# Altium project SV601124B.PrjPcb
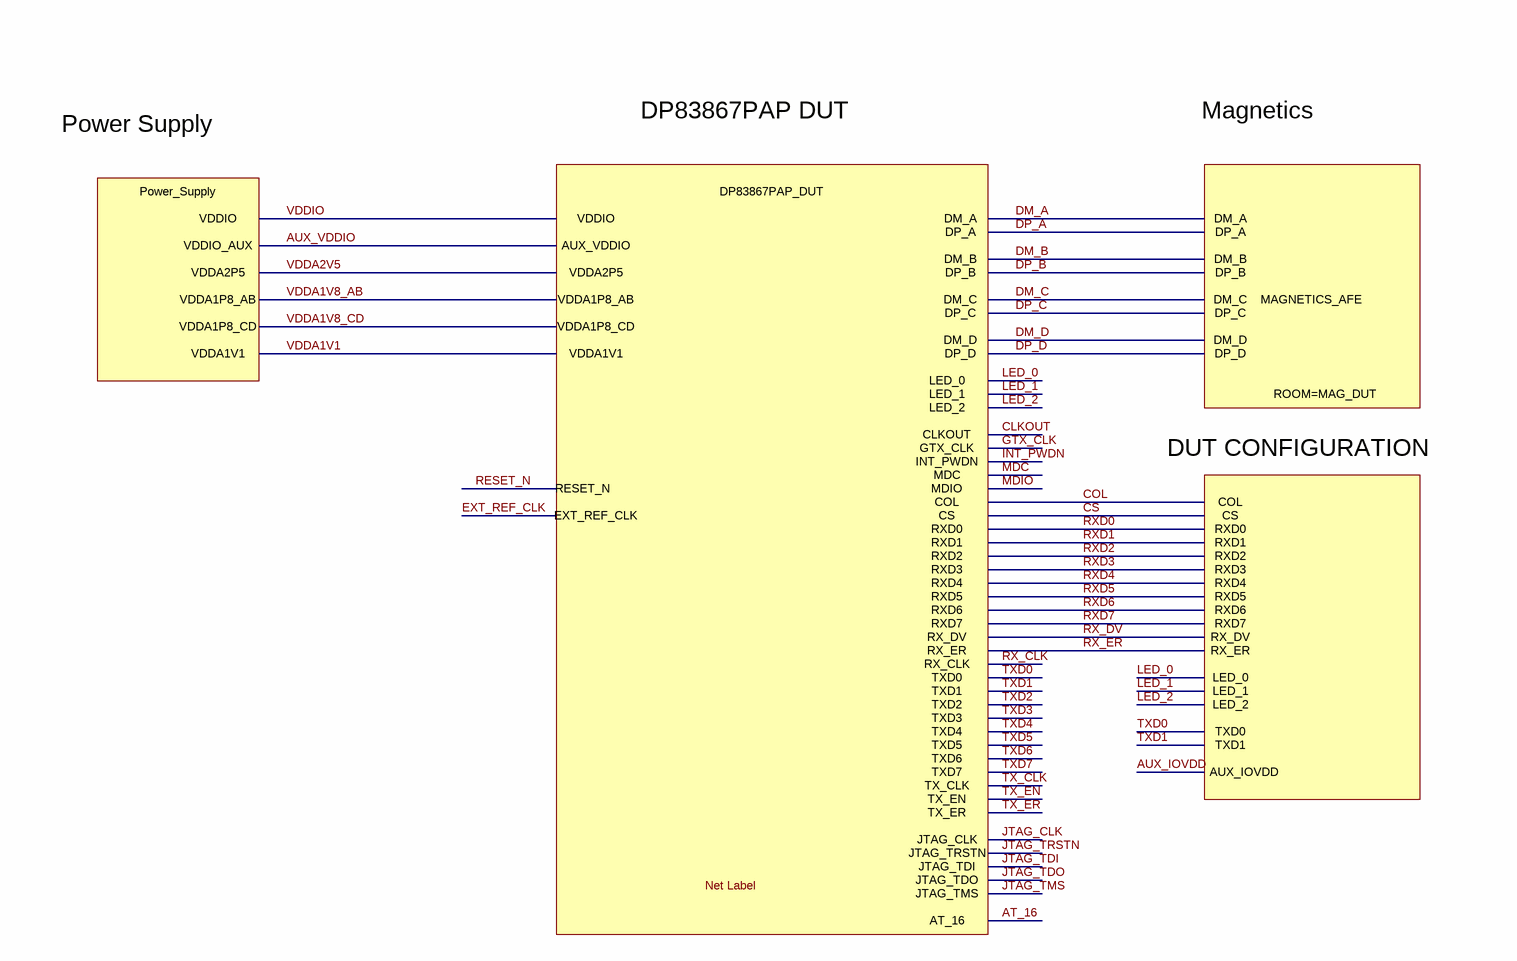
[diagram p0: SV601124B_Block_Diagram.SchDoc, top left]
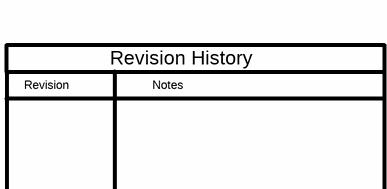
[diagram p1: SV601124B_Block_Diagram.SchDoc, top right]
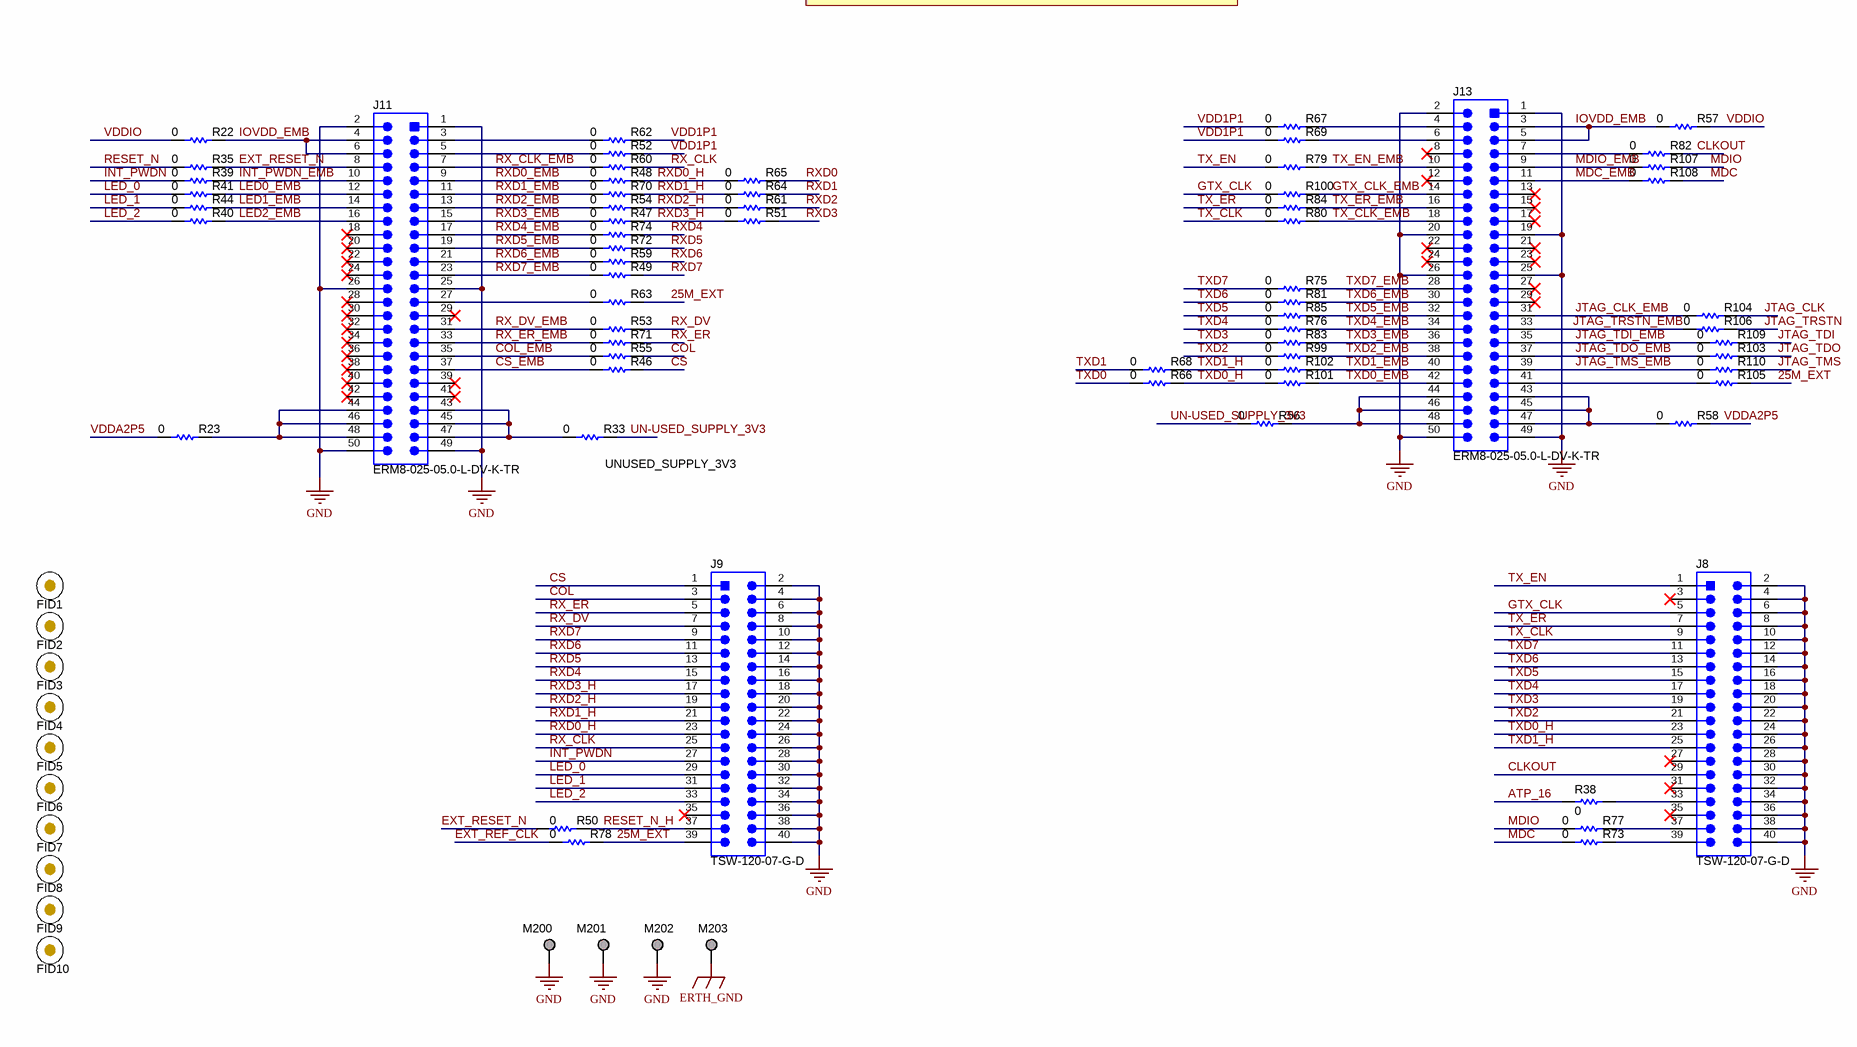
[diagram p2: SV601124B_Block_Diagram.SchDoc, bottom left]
TID: N/A; TechSupport: http://www.ti.com/support; SCH_Rev: B; PRJ_Title: DP83867IRPAP-EVM; PRJ_Number: SV601124; PRJ_Engineer: Dan Suckow; PRJ_Customer: Public Release; PCB_Rev: B; PCB_Layout: Matthew Dillingham; CopyrightYear: 2014
5 sheets, 246 parts. Net scope: global (net labels, ports and power ports of the same name join across sheets).
Board file: SV601124B.PcbDoc
Sheets:
  SV601124B_Block_Diagram.SchDoc
  SV601124B_DP83867IRPAP.SchDoc
  SV601124B_Power_Supply.SchDoc
  SV601124B_Configuration pins.SchDoc
  SV601124B_Magnetics.SchDoc

## Sheet SV601124B_Block_Diagram.SchDoc
size 431 x 406 mm; Date: Not shown in title block; ApprovedBy: Not shown in title block; CheckedBy: Not shown in title block; Author: Not shown in title block; CompanyName: Not shown in title block; Engineer: Not shown in title block; Organization: Not shown in title block; Address1: Not shown in title block; Address2: Not shown in title block; Address3: Not shown in title block; Address4: Not shown in title block; DocumentNumber: 1; Revision: Use project parameter SCH_Rev; SheetNumber: 1; SheetTotal: 3; PageSetup: Record=PageOptions¦CenterHorizontal=True¦CenterVertical=True¦PrintScale=1.00¦XCorrection=1.00¦YCorrection=1.00¦PrintKind=0¦BorderSize=5000000¦LeftOffset=0¦BottomOffset=0¦Orientation=2¦PaperLength=1000¦PaperWidth=1000¦Scale=100¦PaperSource=15¦PrintQuality=600¦MediaType=1¦DitherType=10¦PrintScaleMode=1¦PaperKind=Letter

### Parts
FID1  Fiducial  [Fiducial10-20]  (value not drawn)
FID2  Fiducial  [Fiducial10-20]  (value not drawn)
FID3  Fiducial  [Fiducial10-20]  (value not drawn)
FID4  Fiducial  [Fiducial10-20]  (value not drawn)
FID5  Fiducial  [Fiducial10-20]  (value not drawn)
FID6  Fiducial  [Fiducial10-20]  (value not drawn)
FID7  Fiducial  [Fiducial10-20]  (value not drawn)
FID8  Fiducial  [Fiducial10-20]  (value not drawn)
FID9  Fiducial  [Fiducial10-20]  (value not drawn)
FID10  Fiducial  [Fiducial10-20]  (value not drawn)
J8  TSW-120-07-G-D  [TSW-120-07-G-D]
J9  TSW-120-07-G-D  [TSW-120-07-G-D]
J11  ERM8-025-05.0-L-DV-K-TR  [SAMTEC_ERM8-025-05_0-L-DV-K-TR]
J13  ERM8-025-05.0-L-DV-K-TR  [SAMTEC_ERM8-025-05_0-L-DV-K-TR]
M200  TESTPOINT  [TESTPOINT]  (value not drawn)  (no BOM)
M201  TESTPOINT  [TESTPOINT]  (value not drawn)  (no BOM)
M202  TESTPOINT  [TESTPOINT]  (value not drawn)  (no BOM)
M203  TESTPOINT  [TESTPOINT]  (value not drawn)  (no BOM)
R22  ValueDisplayed: 0  [0603]  (hidden comment: RC0603JR-070RL)
R23  ValueDisplayed: 0  [0603L]  (hidden comment: RC0603JR-070RL)
R33  ValueDisplayed: 0  [0603L]  (hidden comment: RC0603JR-070RL)
R35  ValueDisplayed: 0  [0402L]  (hidden comment: CRCW04020000Z0ED)
R38  ValueDisplayed: 0  [0402]  (hidden comment: CRCW04020000Z0ED)
R39  ValueDisplayed: 0  [0402L]  (hidden comment: CRCW04020000Z0ED)
R40  ValueDisplayed: 0  [0402]  (hidden comment: CRCW04020000Z0ED)
R41  ValueDisplayed: 0  [0402L]  (hidden comment: CRCW04020000Z0ED)
R44  ValueDisplayed: 0  [0402]  (hidden comment: CRCW04020000Z0ED)
R46  ValueDisplayed: 0  [0402]  (hidden comment: CRCW04020000Z0ED)
R47  ValueDisplayed: 0  [0402L]  (hidden comment: CRCW04020000Z0ED)
R48  ValueDisplayed: 0  [0402L]  (hidden comment: CRCW04020000Z0ED)
R49  ValueDisplayed: 0  [0402]  (hidden comment: CRCW04020000Z0ED)
R50  ValueDisplayed: 0  [0402]  (hidden comment: CRCW04020000Z0ED)
R51  ValueDisplayed: 0  [0201L]  (hidden comment: ERJ-1GE0R00C)
R52  ValueDisplayed: 0  [0603]  (hidden comment: RC0603JR-070RL)
R53  ValueDisplayed: 0  [0402]  (hidden comment: CRCW04020000Z0ED)
R54  ValueDisplayed: 0  [0402L]  (hidden comment: CRCW04020000Z0ED)
R55  ValueDisplayed: 0  [0402]  (hidden comment: CRCW04020000Z0ED)
R56  ValueDisplayed: 0  [0603]  (hidden comment: RC0603JR-070RL)
R57  ValueDisplayed: 0  [0603L]  (hidden comment: RC0603JR-070RL)
R58  ValueDisplayed: 0  [0603]  (hidden comment: RC0603JR-070RL)
R59  ValueDisplayed: 0  [0402]  (hidden comment: CRCW04020000Z0ED)
R60  ValueDisplayed: 0  [0402]  (hidden comment: CRCW04020000Z0ED)
R61  ValueDisplayed: 0  [0201L]  (hidden comment: ERJ-1GE0R00C)
R62  ValueDisplayed: 0  [0603]  (hidden comment: RC0603JR-070RL)
R63  ValueDisplayed: 0  [0603L]  (hidden comment: RC0603JR-070RL)
R64  ValueDisplayed: 0  [0201L]  (hidden comment: ERJ-1GE0R00C)
R65  ValueDisplayed: 0  [0201L]  (hidden comment: ERJ-1GE0R00C)
R66  ValueDisplayed: 0  [0201L]  (hidden comment: ERJ-1GE0R00C)
R67  ValueDisplayed: 0  [0402]  (hidden comment: CRCW04020000Z0ED)
R68  ValueDisplayed: 0  [0201L]  (hidden comment: ERJ-1GE0R00C)
R69  ValueDisplayed: 0  [0402]  (hidden comment: CRCW04020000Z0ED)
R70  ValueDisplayed: 0  [0402L]  (hidden comment: CRCW04020000Z0ED)
R71  ValueDisplayed: 0  [0402]  (hidden comment: CRCW04020000Z0ED)
R72  ValueDisplayed: 0  [0402]  (hidden comment: CRCW04020000Z0ED)
R73  ValueDisplayed: 0  [0402]  (hidden comment: CRCW04020000Z0ED)
R74  ValueDisplayed: 0  [0402]  (hidden comment: CRCW04020000Z0ED)
R75  ValueDisplayed: 0  [0402]  (hidden comment: CRCW04020000Z0ED)
R76  ValueDisplayed: 0  [0402]  (hidden comment: CRCW04020000Z0ED)
R77  ValueDisplayed: 0  [0402]  (hidden comment: CRCW04020000Z0ED)
R78  ValueDisplayed: 0  [0603]  (hidden comment: RC0603JR-070RL)
R79  ValueDisplayed: 0  [0402]  (hidden comment: CRCW04020000Z0ED)
R80  ValueDisplayed: 0  [0402]  (hidden comment: CRCW04020000Z0ED)
R81  ValueDisplayed: 0  [0402]  (hidden comment: CRCW04020000Z0ED)
R82  ValueDisplayed: 0  [0402]  (hidden comment: CRCW04020000Z0ED)
R83  ValueDisplayed: 0  [0402]  (hidden comment: CRCW04020000Z0ED)
R84  ValueDisplayed: 0  [0402]  (hidden comment: CRCW04020000Z0ED)
R85  ValueDisplayed: 0  [0402]  (hidden comment: CRCW04020000Z0ED)
R99  ValueDisplayed: 0  [0402L]  (hidden comment: CRCW04020000Z0ED)
R100  ValueDisplayed: 0  [0402]  (hidden comment: CRCW04020000Z0ED)
R101  ValueDisplayed: 0  [0402]  (hidden comment: CRCW04020000Z0ED)
R102  ValueDisplayed: 0  [0402]  (hidden comment: CRCW04020000Z0ED)
R103  ValueDisplayed: 0  [0402L]  (hidden comment: CRCW04020000Z0ED)
R104  ValueDisplayed: 0  [0402]  (hidden comment: CRCW04020000Z0ED)
R105  ValueDisplayed: 0  [0603]  (hidden comment: RC0603JR-070RL)
R106  ValueDisplayed: 0  [0402]  (hidden comment: CRCW04020000Z0ED)
R107  ValueDisplayed: 0  [0402]  (hidden comment: CRCW04020000Z0ED)
R108  ValueDisplayed: 0  [0402]  (hidden comment: CRCW04020000Z0ED)
R109  ValueDisplayed: 0  [0402L]  (hidden comment: CRCW04020000Z0ED)
R110  ValueDisplayed: 0  [0402]  (hidden comment: CRCW04020000Z0ED)

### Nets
ERTH_GND: M203.1
GND: J8.2 J8.4 J8.6 J8.8 J8.10 J8.12 J8.14 J8.16 J8.18 J8.20 J8.22 J8.24 J8.26 J8.28 J8.30 J8.32 J8.34 J8.36 J8.38 J8.40 J9.2 J9.4 J9.6 J9.8 J9.10 J9.12 J9.14 J9.16 J9.18 J9.20 J9.22 J9.24 J9.26 J9.28 J9.30 J9.32 J9.34 J9.36 J9.38 J9.40 J11.1 J11.2 J11.25 J11.26 J11.49 J11.50 J13.1 J13.2 J13.19 J13.20 J13.25 J13.26 J13.49 J13.50 M200.1 M201.1 M202.1
25M_EXT: J9.39 R63.2 R78.2 R105.2
ATP_16: R38.2
CLKOUT: J8.29 R82.2
COL: J9.3 R55.1
COL_EMB: J11.35 R55.2
CS: J9.1 R46.1
CS_EMB: J11.37 R46.2
EXT_REF_CLK: R78.1
EXT_RESET_N: J11.8 R35.2 R50.2
GTX_CLK: J8.5 R100.1
GTX_CLK_EMB: J13.14 R100.2
INT_PWDN: J9.27 R39.2
INT_PWDN_EMB: J11.10 R39.1
IOVDD_EMB: J11.4 J11.6 J13.3 J13.5 R22.2 R57.1
JTAG_CLK: R104.2
JTAG_CLK_EMB: J13.31 R104.1
JTAG_TDI: R109.2
JTAG_TDI_EMB: J13.35 R109.1
JTAG_TDO: R103.2
JTAG_TDO_EMB: J13.37 R103.1
JTAG_TMS: R110.2
JTAG_TMS_EMB: J13.39 R110.1
JTAG_TRSTN: R106.2
JTAG_TRSTN_EMB: J13.33 R106.1
LED0_EMB: J11.12 R41.2
LED1_EMB: J11.14 R44.2
LED2_EMB: J11.16 R40.2
LED_0: J9.29 R41.1
LED_1: J9.31 R44.1
LED_2: J9.33 R40.1
MDC: R73.1 R108.2
MDC_EMB: J13.11 R108.1
MDIO: R77.1 R107.2
MDIO_EMB: J13.9 R107.1
RESET_N: R35.1
RESET_N_H: J9.37 R50.1
RX_CLK: J9.25 R60.1
RX_CLK_EMB: J11.7 R60.2
RX_DV: J9.7 R53.2
RX_DV_EMB: J11.31 R53.1
RX_ER: J9.5 R71.2
RX_ER_EMB: J11.33 R71.1
RXD0: R65.1
RXD0_EMB: J11.9 R48.2
RXD0_H: J9.23 R48.1 R65.2
RXD1: R64.1
RXD1_EMB: J11.11 R70.1
RXD1_H: J9.21 R64.2 R70.2
RXD2: R61.1
RXD2_EMB: J11.13 R54.2
RXD2_H: J9.19 R54.1 R61.2
RXD3: R51.1
RXD3_EMB: J11.15 R47.2
RXD3_H: J9.17 R47.1 R51.2
RXD4: J9.15 R74.2
RXD4_EMB: J11.17 R74.1
RXD5: J9.13 R72.2
RXD5_EMB: J11.19 R72.1
RXD6: J9.11 R59.1
RXD6_EMB: J11.21 R59.2
RXD7: J9.9 R49.1
RXD7_EMB: J11.23 R49.2
TX_CLK: J8.9 R80.1
TX_CLK_EMB: J13.18 R80.2
TX_EN: J8.1 R79.1
TX_EN_EMB: J13.10 R79.2
TX_ER: J8.7 R84.1
TX_ER_EMB: J13.16 R84.2
TXD0: R66.1
TXD0_EMB: J13.42 R101.2
TXD0_H: J8.23 R66.2 R101.1
TXD1: R68.1
TXD1_EMB: J13.40 R102.2
TXD1_H: J8.25 R68.2 R102.1
TXD2: J8.21 R99.1
TXD2_EMB: J13.38 R99.2
TXD3: J8.19 R83.1
TXD3_EMB: J13.36 R83.2
TXD4: J8.17 R76.1
TXD4_EMB: J13.34 R76.2
TXD5: J8.15 R85.1
TXD5_EMB: J13.32 R85.2
TXD6: J8.13 R81.1
TXD6_EMB: J13.30 R81.2
TXD7: J8.11 R75.1
TXD7_EMB: J13.28 R75.2
UN-USED_SUPPLY_3V3: R33.2 R56.1
VDD1P1: R52.2 R62.2 R67.1 R69.1
VDDA2P5: R23.1 R58.2
VDDIO: R22.1 R57.2
NetJ8_33: J8.33 R38.1
NetJ8_37: J8.37 R77.2
NetJ8_39: J8.39 R73.2
NetJ11_3: J11.3 R62.1
NetJ11_5: J11.5 R52.1
NetJ11_27: J11.27 R63.1
NetJ11_43: J11.43 J11.45 J11.47 R33.1
NetJ11_44: J11.44 J11.46 J11.48 R23.2
NetJ13_4: J13.4 R67.2
NetJ13_6: J13.6 R69.2
NetJ13_7: J13.7 R82.1
NetJ13_41: J13.41 R105.1
NetJ13_43: J13.43 J13.45 J13.47 R58.1
NetJ13_44: J13.44 J13.46 J13.48 R56.2

Not connected (* = marked no-connect by the designer): J8 3* 27* 31* 35*; J9 35*; J11 18* 20* 22* 24* 28* 29* 30* 32* 34* 36* 38* 39* 40* 41* 42*; J13 8* 12* 13* 15* 17* 21* 22* 23* 24* 27* 29*

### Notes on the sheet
- Revision
- Notes
- Revision History
- DP83867PAP DUT
- Magnetics
- Power Supply
- Power_Supply
- VDDIO
- VDDIO_AUX
- AUX_VDDIO
- DP83867PAP_DUT
- DM_A
- DP_A
- VDDA2P5
- VDDA1P8_AB
- DM_B
- DP_B
- DM_C
- DP_C
- MAGNETICS_AFE
- VDDA1P8_CD
- VDDA1V1
- LED_0
- DM_D
- DP_D
- LED_1
- LED_2
- CLKOUT
- GTX_CLK
- DUT CONFIGURATION
- ROOM=MAG_DUT
- RESET_N
- EXT_REF_CLK
- INT_PWDN
- MDC
- MDIO
- COL
- CS
- RXD0
- RXD1
- RXD2
- RXD3
- RXD4
- RXD5
- RXD6
- RXD7
- RX_DV
- RX_ER
- RX_CLK
- TXD0
- TXD1
- TXD2
- TXD3
- TXD4
- TXD5
- TXD6
- TXD7
- TX_CLK
- AUX_IOVDD
- TX_EN
- TX_ER
- JTAG_CLK
- JTAG_TRSTN
- JTAG_TDI
- JTAG_TDO
- JTAG_TMS
- AT_16
- (near R33) UNUSED_SUPPLY_3V3
- Labels drawn without touching a wire or pin: Net Label

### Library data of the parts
FID1-FID10 = Fiducial: Fiducial mark.  There is nothing to buy or mount.; SymbolCreator: codlsc
J8 J9 = TSW-120-07-G-D: Header, 100mil, 20x2, Gold, TH; Manufacturer: Samtec; SymbolCreator: a0412235; U/M: EA
J11 J13 = ERM8-025-05.0-L-DV-K-TR: CONN MICRO HS TERM STRP HDR 50 POS; Manufacturer: Samtec; SymbolCreator: a0799628; CompType: Header; U/M: EA
M200-M203 = TESTPOINT: TEST POINT.  No entry in BOM.
R22 R23 R33 R52 R56-R58 R62 R63 R78 R105 = RC0603JR-070RL: RES, 0, 5%, 0.1 W, 0603; Manufacturer: Yageo America; CompType: Resistor; Value: 0; Value_Code: 0000; Tolerance_%: 5; Power_W: 0.1; Value2: 0.1W; VDC_V: 50; TempCo: 200 ppm/C; EIA_Code: E24; U/M: EA
R35 R38-R41 R44 R46-R50 R53-R55 R59 R60 R67 R69-R77 R79-R85 R99-R104 R106-R110 = CRCW04020000Z0ED: RES, 0, 5%, 0.063 W, 0402; Manufacturer: Vishay-Dale; CompType: Resistor; Value: 0; Value_Code: 0000; Tolerance_%: 5; Power_W: 0.063; Value2: 0.063W; VDC_V: 50; TempCo: 200 ppm/C; EIA_Code: E24; U/M: EA
R51 R61 R64-R66 R68 = ERJ-1GE0R00C: RES, 0, 5%, 0.05 W, 0201; Manufacturer: Panasonic; CompType: Resistor; Value: 0; Value_Code: 0000; Tolerance_%: 5; Power_W: 0.05; Value2: 0.05W; VDC_V: 15; TempCo: 600 ppm/C; EIA_Code: E24; U/M: EA

## Sheet SV601124B_DP83867IRPAP.SchDoc
size 431 x 279 mm; Date: Not shown in title block; ApprovedBy: Not shown in title block; CheckedBy: Not shown in title block; Author: Not shown in title block; CompanyName: Not shown in title block; Engineer: Not shown in title block; Organization: Not shown in title block; Address1: Not shown in title block; Address2: Not shown in title block; Address3: Not shown in title block; Address4: Not shown in title block; DocumentNumber: 1; Revision: Use project parameter SCH_Rev; SheetNumber: 2; SheetTotal: 3; PageSetup: Record=PageOptions¦CenterHorizontal=True¦CenterVertical=True¦PrintScale=1.00¦XCorrection=1.00¦YCorrection=1.00¦PrintKind=0¦BorderSize=5000000¦LeftOffset=0¦BottomOffset=0¦Orientation=2¦PaperLength=1000¦PaperWidth=1000¦Scale=100¦PaperSource=15¦PrintQuality=600¦MediaType=1¦DitherType=10¦PaperKind=Letter¦PrintScaleMode=1
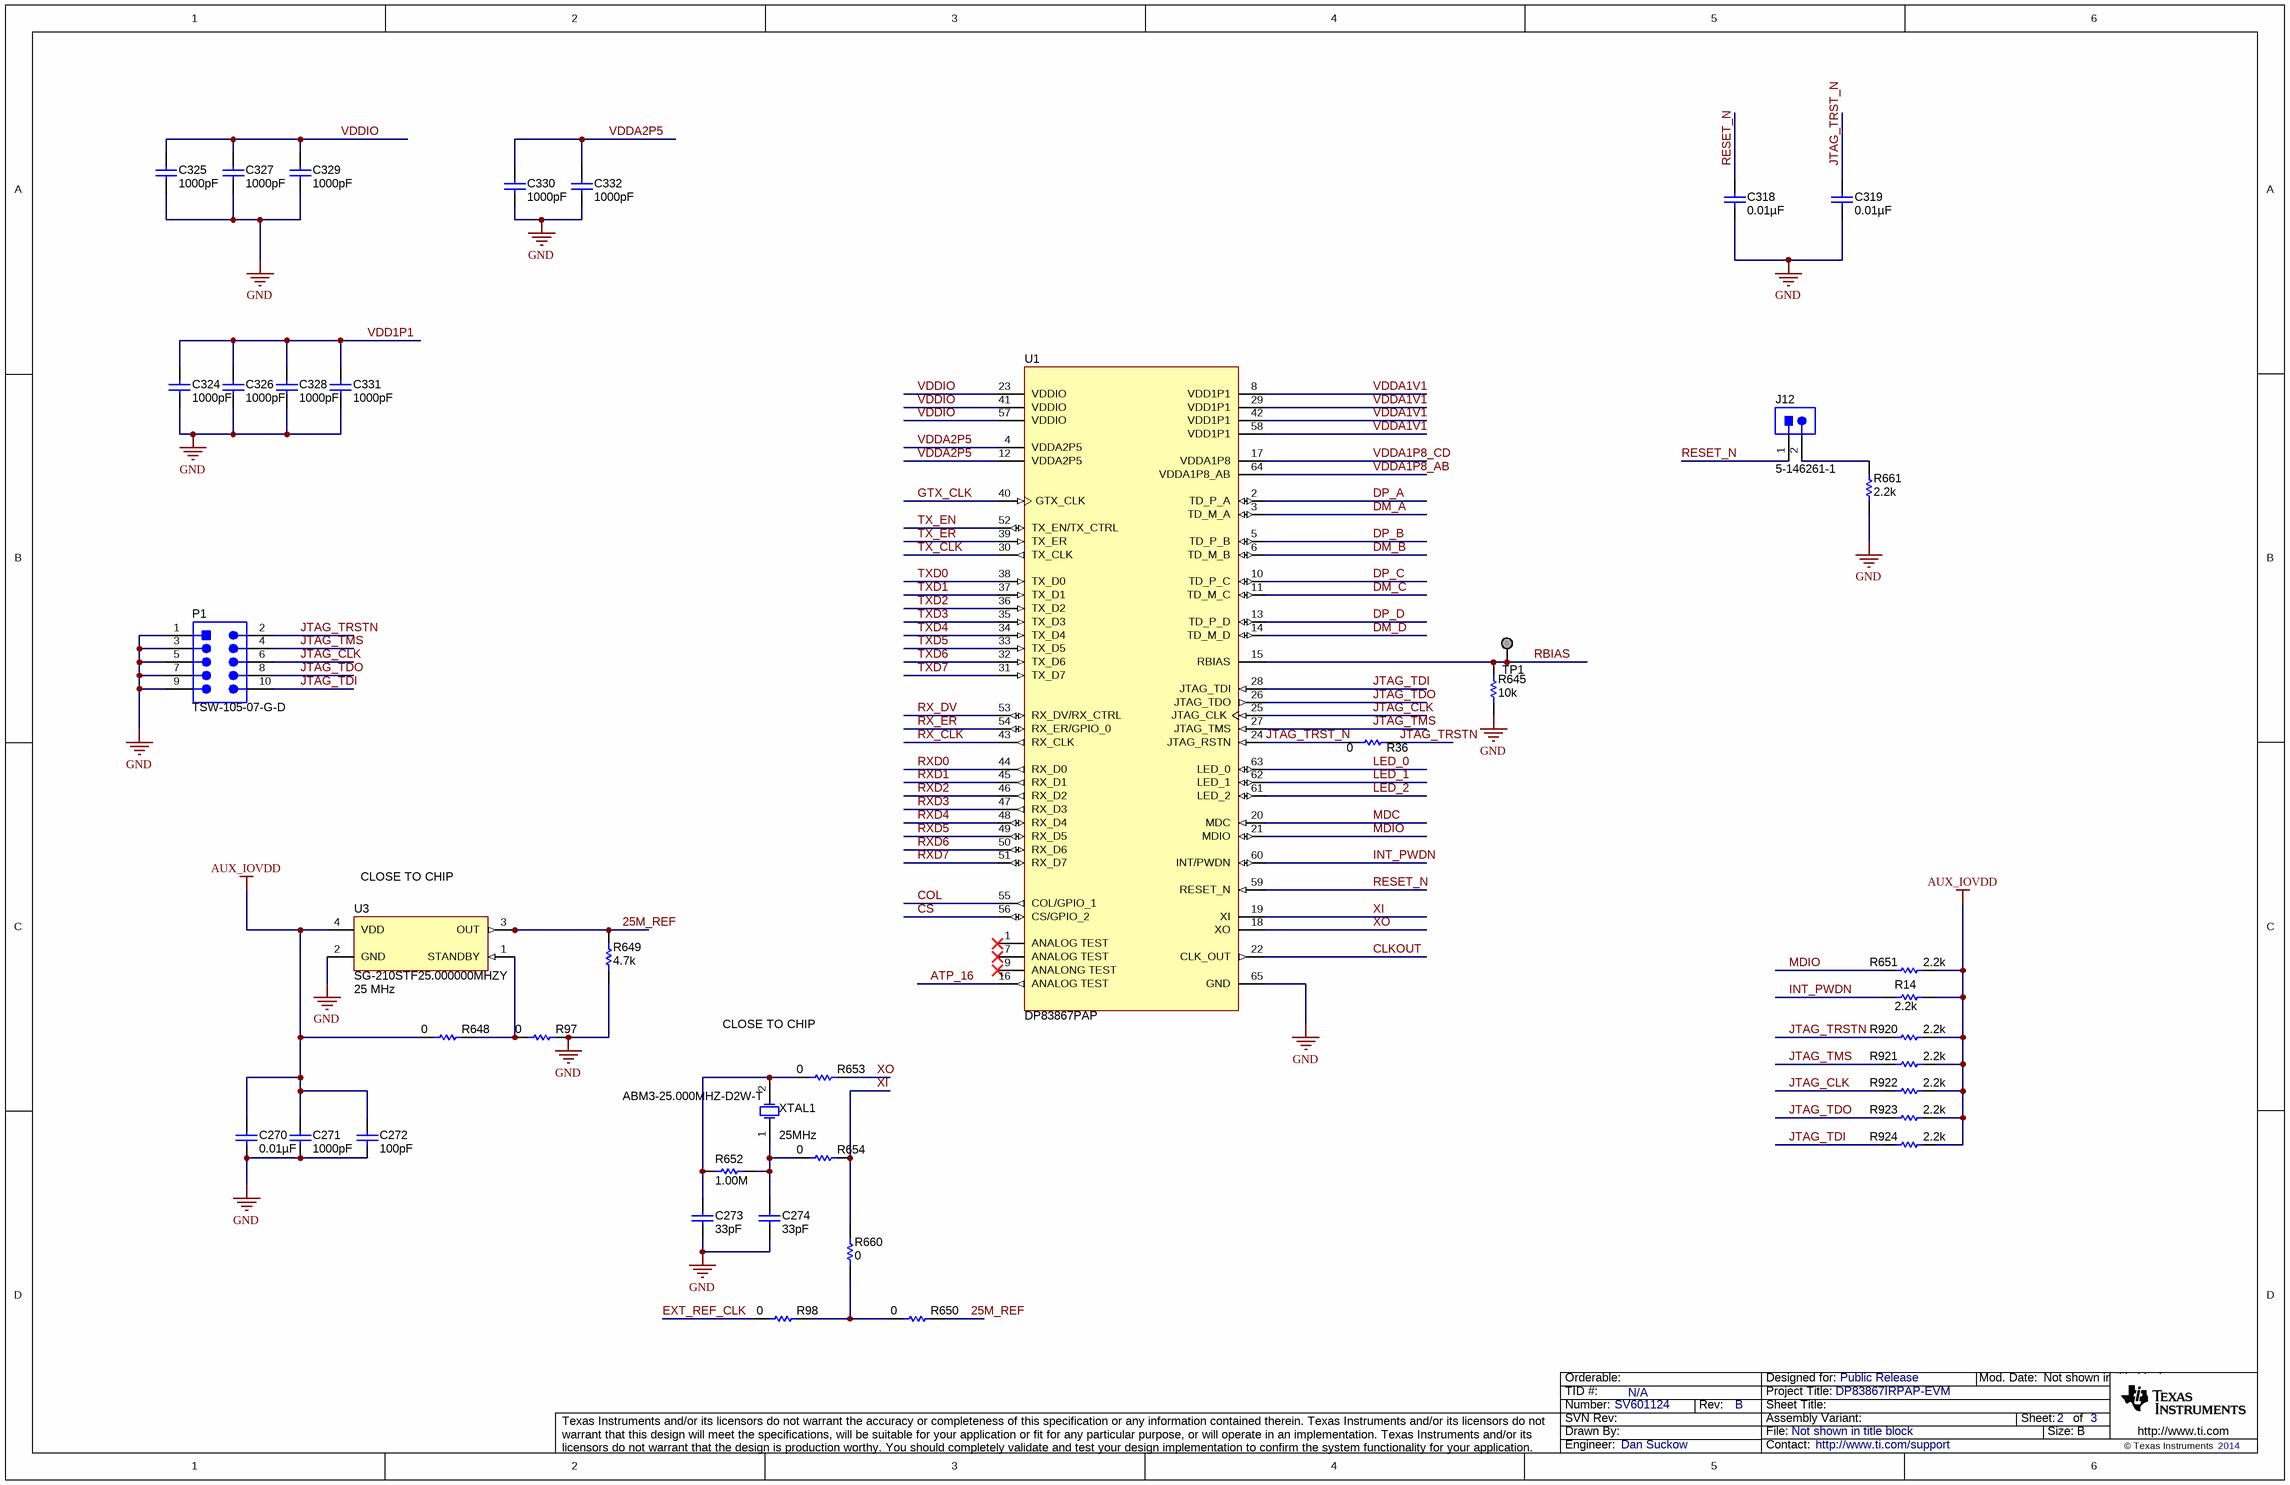
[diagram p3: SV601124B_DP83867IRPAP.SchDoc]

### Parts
C270  ValueDisplayed: 0.01µF  [0402]  (hidden comment: C0402C103J5RACTU)
C271  ValueDisplayed: 1000pF  [0402]  (hidden comment: C0402C102J3RACTU)
C272  ValueDisplayed: 100pF  [0402]  (hidden comment: CC0402JRNPO9BN101)
C273  ValueDisplayed: 33pF  [0603_950]  (hidden comment: CL10C330FB8NNNC)
C274  ValueDisplayed: 33pF  [0603_950]  (hidden comment: CL10C330FB8NNNC)
C318  ValueDisplayed: 0.01µF  [0402L]  (hidden comment: GRM155R71H103KA88D)
C319  ValueDisplayed: 0.01µF  [0402]  (hidden comment: GRM155R71H103KA88D)
C324  ValueDisplayed: 1000pF  [0402L]  (hidden comment: C0402C102J3RACTU)
C325  ValueDisplayed: 1000pF  [0402L]  (hidden comment: C0402C102J3RACTU)
C326  ValueDisplayed: 1000pF  [0402]  (hidden comment: C0402C102J3RACTU)
C327  ValueDisplayed: 1000pF  [0402]  (hidden comment: C0402C102J3RACTU)
C328  ValueDisplayed: 1000pF  [0402]  (hidden comment: C0402C102J3RACTU)
C329  ValueDisplayed: 1000pF  [0402]  (hidden comment: C0402C102J3RACTU)
C330  ValueDisplayed: 1000pF  [0402L]  (hidden comment: C0402C102J3RACTU)
C331  ValueDisplayed: 1000pF  [0402L]  (hidden comment: C0402C102J3RACTU)
C332  ValueDisplayed: 1000pF  [0402L]  (hidden comment: C0402C102J3RACTU)
J12  5-146261-1  [CONN_5-146261-1]
P1  TSW-105-07-G-D  [TSW-105-07-G-D]
R14  ValueDisplayed: 2.2k  [0402L]  (hidden comment: CRCW04022K20JNED)
R36  ValueDisplayed: 0  [0402]  (hidden comment: RC0402JR-070RL)
R97  ValueDisplayed: 0  [0603]  (hidden comment: RC0603JR-070RL)
R98  ValueDisplayed: 0  [0603L]  (hidden comment: RC0603JR-070RL)
R645  ValueDisplayed: 10k  [0603]  (hidden comment: RC0603JR-0710KL)
R648  ValueDisplayed: 0  [0603]  (hidden comment: RC0603JR-070RL)
R649  ValueDisplayed: 4.7k  [0603L]  (hidden comment: CRCW06034K70JNEA)
R650  ValueDisplayed: 0  [0603L]  (hidden comment: RC0603JR-070RL)
R651  ValueDisplayed: 2.2k  [0402]  (hidden comment: CRCW04022K20JNED)
R652  ValueDisplayed: 1.00M  [0402]  (hidden comment: RC0402FR-071ML)
R653  ValueDisplayed: 0  [0603]  (hidden comment: RC0603JR-070RL)
R654  ValueDisplayed: 0  [0603]  (hidden comment: RC0603JR-070RL)
R660  ValueDisplayed: 0  [0603L]  (hidden comment: RC0603JR-070RL)
R661  ValueDisplayed: 2.2k  [0402]  (hidden comment: CRCW04022K20JNED)
R920  ValueDisplayed: 2.2k  [0402]  (hidden comment: CRCW04022K20JNED)
R921  ValueDisplayed: 2.2k  [0402]  (hidden comment: CRCW04022K20JNED)
R922  ValueDisplayed: 2.2k  [0402]  (hidden comment: CRCW04022K20JNED)
R923  ValueDisplayed: 2.2k  [0402]  (hidden comment: CRCW04022K20JNED)
R924  ValueDisplayed: 2.2k  [0402]  (hidden comment: CRCW04022K20JNED)
TP1  TESTPOINT  [TP_25MIL-SMT]  (value not drawn)  (no BOM)
U1  DP83867PAP  [PAP0064M_N]
U3  SG-210STF25.000000MHZY  Frequency: 25 MHz  [Epson_SG-210]
XTAL1  ABM3-25.000MHZ-D2W-T  Frequency: 25MHz  [XTAL_ABM3]

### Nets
AUX_IOVDD: C270.2 C271.2 C272.2 R14.2 R648.1 R651.1 R920.1 R921.1 R922.1 R923.1 R924.1 U3.4(VDD)
GND: C270.1 C271.1 C272.1 C273.2 C274.2 C318.1 C319.1 C324.1 C325.1 C326.1 C327.1 C328.1 C329.1 C330.1 C331.1 C332.1 P1.1 P1.3 P1.5 P1.7 P1.9 R97.2 R645.1 R649.1 R661.1 U1.65(GND) U3.2(GND)
25M_REF: R649.2 R650.2 U3.3(OUT)
ATP_16: U1.16(ANALOG_TEST)
CLKOUT: U1.22(CLK_OUT)
COL: U1.55(COL/GPIO_1)
CS: U1.56(CS/GPIO_2)
DM_A: U1.3(TD_M_A)
DM_B: U1.6(TD_M_B)
DM_C: U1.11(TD_M_C)
DM_D: U1.14(TD_M_D)
DP_A: U1.2(TD_P_A)
DP_B: U1.5(TD_P_B)
DP_C: U1.10(TD_P_C)
DP_D: U1.13(TD_P_D)
EXT_REF_CLK: R98.1
GTX_CLK: U1.40(GTX_CLK)
INT_PWDN: R14.1 U1.60(INT/PWDN)
JTAG_CLK: P1.6 R922.2 U1.25(JTAG_CLK)
JTAG_TDI: P1.10 R924.2 U1.28(JTAG_TDI)
JTAG_TDO: P1.8 R923.2 U1.26(JTAG_TDO)
JTAG_TMS: P1.4 R921.2 U1.27(JTAG_TMS)
JTAG_TRST_N: C319.2 R36.2 U1.24(JTAG_RSTN)
JTAG_TRSTN: P1.2 R36.1 R920.2
LED_0: U1.63(LED_0)
LED_1: U1.62(LED_1)
LED_2: U1.61(LED_2)
MDC: U1.20(MDC)
MDIO: R651.2 U1.21(MDIO)
RBIAS: R645.2 TP1.1 U1.15(RBIAS)
RESET_N: C318.2 J12.1 U1.59(RESET_N)
RX_CLK: U1.43(RX_CLK)
RX_DV: U1.53(RX_DV/RX_CTRL)
RX_ER: U1.54(RX_ER/GPIO_0)
RXD0: U1.44(RX_D0)
RXD1: U1.45(RX_D1)
RXD2: U1.46(RX_D2)
RXD3: U1.47(RX_D3)
RXD4: U1.48(RX_D4)
RXD5: U1.49(RX_D5)
RXD6: U1.50(RX_D6)
RXD7: U1.51(RX_D7)
TX_CLK: U1.30(TX_CLK)
TX_EN: U1.52(TX_EN/TX_CTRL)
TX_ER: U1.39(TX_ER)
TXD0: U1.38(TX_D0)
TXD1: U1.37(TX_D1)
TXD2: U1.36(TX_D2)
TXD3: U1.35(TX_D3)
TXD4: U1.34(TX_D4)
TXD5: U1.33(TX_D5)
TXD6: U1.32(TX_D6)
TXD7: U1.31(TX_D7)
VDD1P1: C324.2 C326.2 C328.2 C331.2
VDDA1P8_AB: U1.64(VDDA1P8_AB)
VDDA1P8_CD: U1.17(VDDA1P8)
VDDA1V1: U1.8(VDD1P1) U1.29(VDD1P1) U1.42(VDD1P1) U1.58(VDD1P1)
VDDA2P5: C330.2 C332.2 U1.4(VDDA2P5) U1.12(VDDA2P5)
VDDIO: C325.2 C327.2 C329.2 U1.23(VDDIO) U1.41(VDDIO) U1.57(VDDIO)
XI: R654.2 R660.1 U1.19(XI)
XO: R653.2 U1.18(XO)
NetC273_1: C273.1 R652.1 R653.1 XTAL1.2(OSC2)
NetC274_1: C274.1 R652.2 R654.1 XTAL1.1(OSC1)
NetJ12_2: J12.2 R661.2
NetR97_1: R97.1 R648.2 U3.1(STANDBY)
NetR98_2: R98.2 R650.1 R660.2

Not connected (* = marked no-connect by the designer): U1 1(ANALOG_TEST)* 7(ANALOG_TEST)* 9(ANALONG_TEST)*

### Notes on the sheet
- (near U3) CLOSE TO CHIP
- CLOSE TO CHIP

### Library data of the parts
C270 = C0402C103J5RACTU: CAP, CERM, 0.01 µF, 50 V, +/- 5%, X7R, 0402; Manufacturer: Kemet; Polarized: N; CompType: Capacitor; Value: 0.01uF; U/M: EA; Cap_F: 0.00000001; Tolerance_%: 5; Value1: Unknown; VDC_V: 50; Value2: 50V; TaMin_C: -55; TaMax_C: 125
C271 C326-C329 = C0402C102J3RACTU: CAP, CERM, 1000 pF, 25 V, +/- 5%, X7R, 0402; Manufacturer: Kemet; Polarized: N; CompType: Capacitor; Value: 1000pF; U/M: EA; Cap_F: 0.000000001; Tolerance_%: 5; Value1: Unknown; VDC_V: 25; Value2: 25V; TaMin_C: -55; TaMax_C: 125
C272 = CC0402JRNPO9BN101: CAP, CERM, 100 pF, 50 V, +/- 5%, C0G/NP0, 0402; Manufacturer: Yageo America; Polarized: N; CompType: Capacitor; Value: 100pF; U/M: EA; Cap_F: 0.0000000001; Tolerance_%: 5; Value1: Unknown; VDC_V: 50; Value2: 50V; TaMin_C: -55; TaMax_C: 125
C273 C274 = CL10C330FB8NNNC: CAP, CERM, 33 pF, 50 V, +/- 1%, C0G/NP0, 0603_950; Manufacturer: Samsung; Polarized: N; CompType: Capacitor; Value: 33pF; U/M: EA; Cap_F: 0.000000000033; Tolerance_%: 1; Value1: Unknown; VDC_V: 50; Value2: 50V; TaMin_C: -55; TaMax_C: 125; Cap_Case: 0603
C318 = GRM155R71H103KA88D: CAP, CERM, 0.01 µF, 50 V, +/- 10%, X7R, 0402; Manufacturer: MuRata; Polarized: N; CompType: Capacitor; Value: 0.01uF; U/M: EA; Cap_F: 0.00000001; Tolerance_%: 10; Value1: Unknown; VDC_V: 50; Value2: 50V; TaMin_C: -55; TaMax_C: 125; Cap_Case: 0402
C319 = GRM155R71H103KA88D: CAP, CERM, 0.01 µF, 50 V, +/- 10%, X7R, 0402; Manufacturer: MuRata; Polarized: N; CompType: Capacitor; Value: 0.01uF; U/M: EA; Cap_F: 0.00000001; Tolerance_%: 10; Value1: Unknown; VDC_V: 50; Value2: 50V; TaMin_C: -55; TaMax_C: 125
C324 C325 C330-C332 = C0402C102J3RACTU: CAP, CERM, 1000 pF, 25 V, +/- 5%, X7R, 0402; Manufacturer: Kemet; Polarized: N; CompType: Capacitor; Value: 1000pF; U/M: EA; Cap_F: 0.000000001; Tolerance_%: 5; Value1: Unknown; VDC_V: 25; Value2: 25V; TaMin_C: -55; TaMax_C: 125; Cap_Case: 0402
J12 = 5-146261-1: Header, 100mil, 2x1, Gold, TH; Manufacturer: TE Connectivity; SymbolCreator: a0412235; U/M: EA
P1 = TSW-105-07-G-D: Header, 100mil, 5x2, Gold, TH; Manufacturer: Samtec; SymbolCreator: a0412235; U/M: EA
R14 R651 R661 R920-R924 = CRCW04022K20JNED: RES, 2.2 k, 5%, 0.063 W, 0402; Manufacturer: Vishay-Dale; CompType: Resistor; Value: 2.2k; Res_ohm: 2200; Value_Code: 2k20; Tolerance_%: 5; Power_W: 0.063; Value2: 0.063W; VDC_V: 50; TempCo: 200 ppm/C; EIA_Code: E24; U/M: EA
R36 = RC0402JR-070RL: RES, 0, 5%, 0.063 W, 0402; Manufacturer: Yageo America; CompType: Resistor; Value: 0; Value_Code: 0000; Tolerance_%: 5; Power_W: 0.063; Value2: 0.063W; VDC_V: 50; TempCo: 200 ppm/C; EIA_Code: E24; U/M: EA
R97 R98 R648 R650 R653 R654 R660 = RC0603JR-070RL: as R22 on sheet SV601124B_Block_Diagram
R645 = RC0603JR-0710KL: RES, 10 k, 5%, 0.1 W, 0603; Manufacturer: Yageo America; CompType: Resistor; Value: 10k; Res_ohm: 10000; Value_Code: 10k0; Tolerance_%: 5; Power_W: 0.1; Value2: 0.1W; VDC_V: 50; TempCo: 100 ppm/C; EIA_Code: E24; U/M: EA
R649 = CRCW06034K70JNEA: RES, 4.7 k, 5%, 0.1 W, 0603; Manufacturer: Vishay-Dale; CompType: Resistor; Value: 4.7k; Res_ohm: 4700; Value_Code: 4k70; Tolerance_%: 5; Power_W: 0.1; Value2: 0.1W; VDC_V: 75; TempCo: 200 ppm/C; EIA_Code: E24; U/M: EA
R652 = RC0402FR-071ML: RES, 1.00 M, 1%, 0.063 W, 0402; Manufacturer: Yageo America; CompType: Resistor; Value: 1.00Meg; Res_ohm: 1000000; Value_Code: 1M00; Tolerance_%: 1; Power_W: 0.063; Value2: 0.063W; TempCo: 100 ppm/C; EIA_Code: E96; U/M: EA
TP1 = TESTPOINT: TEST POINT.  No entry in BOM.
U1 = DP83867PAP: Robust, Low Power 10/100/1000 Ethernet Physical Layer Transceiver, PAP0064M; Manufacturer: Texas Instruments; SymbolCreator: Altium; CompType: IC; U/M: EA
U3 = SG-210STF25.000000MHZY: OSC, 25 MHz, 1.6 to 3.6 V, SMD; Manufacturer: Epson; SymbolCreator: Altium; CompType: Oscillator; U/M: EA; TaMin_C: -40; TaMax_C: 105; Frequency Stability: ±50ppm
XTAL1 = ABM3-25.000MHZ-D2W-T: Crystal, 25 MHz, 18 pF, SMD; Manufacturer: Abracon Corportation; SymbolCreator: a0412235; U/M: EA; TaMin_C: -40; TaMax_C: 85; Frequency Stability: ±25ppm

## Sheet SV601124B_Power_Supply.SchDoc
size 431 x 279 mm; Date: Not shown in title block; ApprovedBy: Not shown in title block; CheckedBy: Not shown in title block; Author: Not shown in title block; CompanyName: Not shown in title block; Engineer: Not shown in title block; Organization: Not shown in title block; Address1: Not shown in title block; Address2: Not shown in title block; Address3: Not shown in title block; Address4: Not shown in title block; DocumentNumber: 1; Revision: Use project parameter SCH_Rev; SheetNumber: 2; SheetTotal: 3; PageSetup: Record=PageOptions¦CenterHorizontal=True¦CenterVertical=True¦PrintScale=1.00¦XCorrection=1.00¦YCorrection=1.00¦PrintKind=0¦BorderSize=5000000¦LeftOffset=0¦BottomOffset=0¦Orientation=2¦PaperLength=1000¦PaperWidth=1000¦Scale=100¦PaperSource=15¦PrintQuality=600¦MediaType=1¦DitherType=10¦PaperKind=Letter¦PrintScaleMode=1
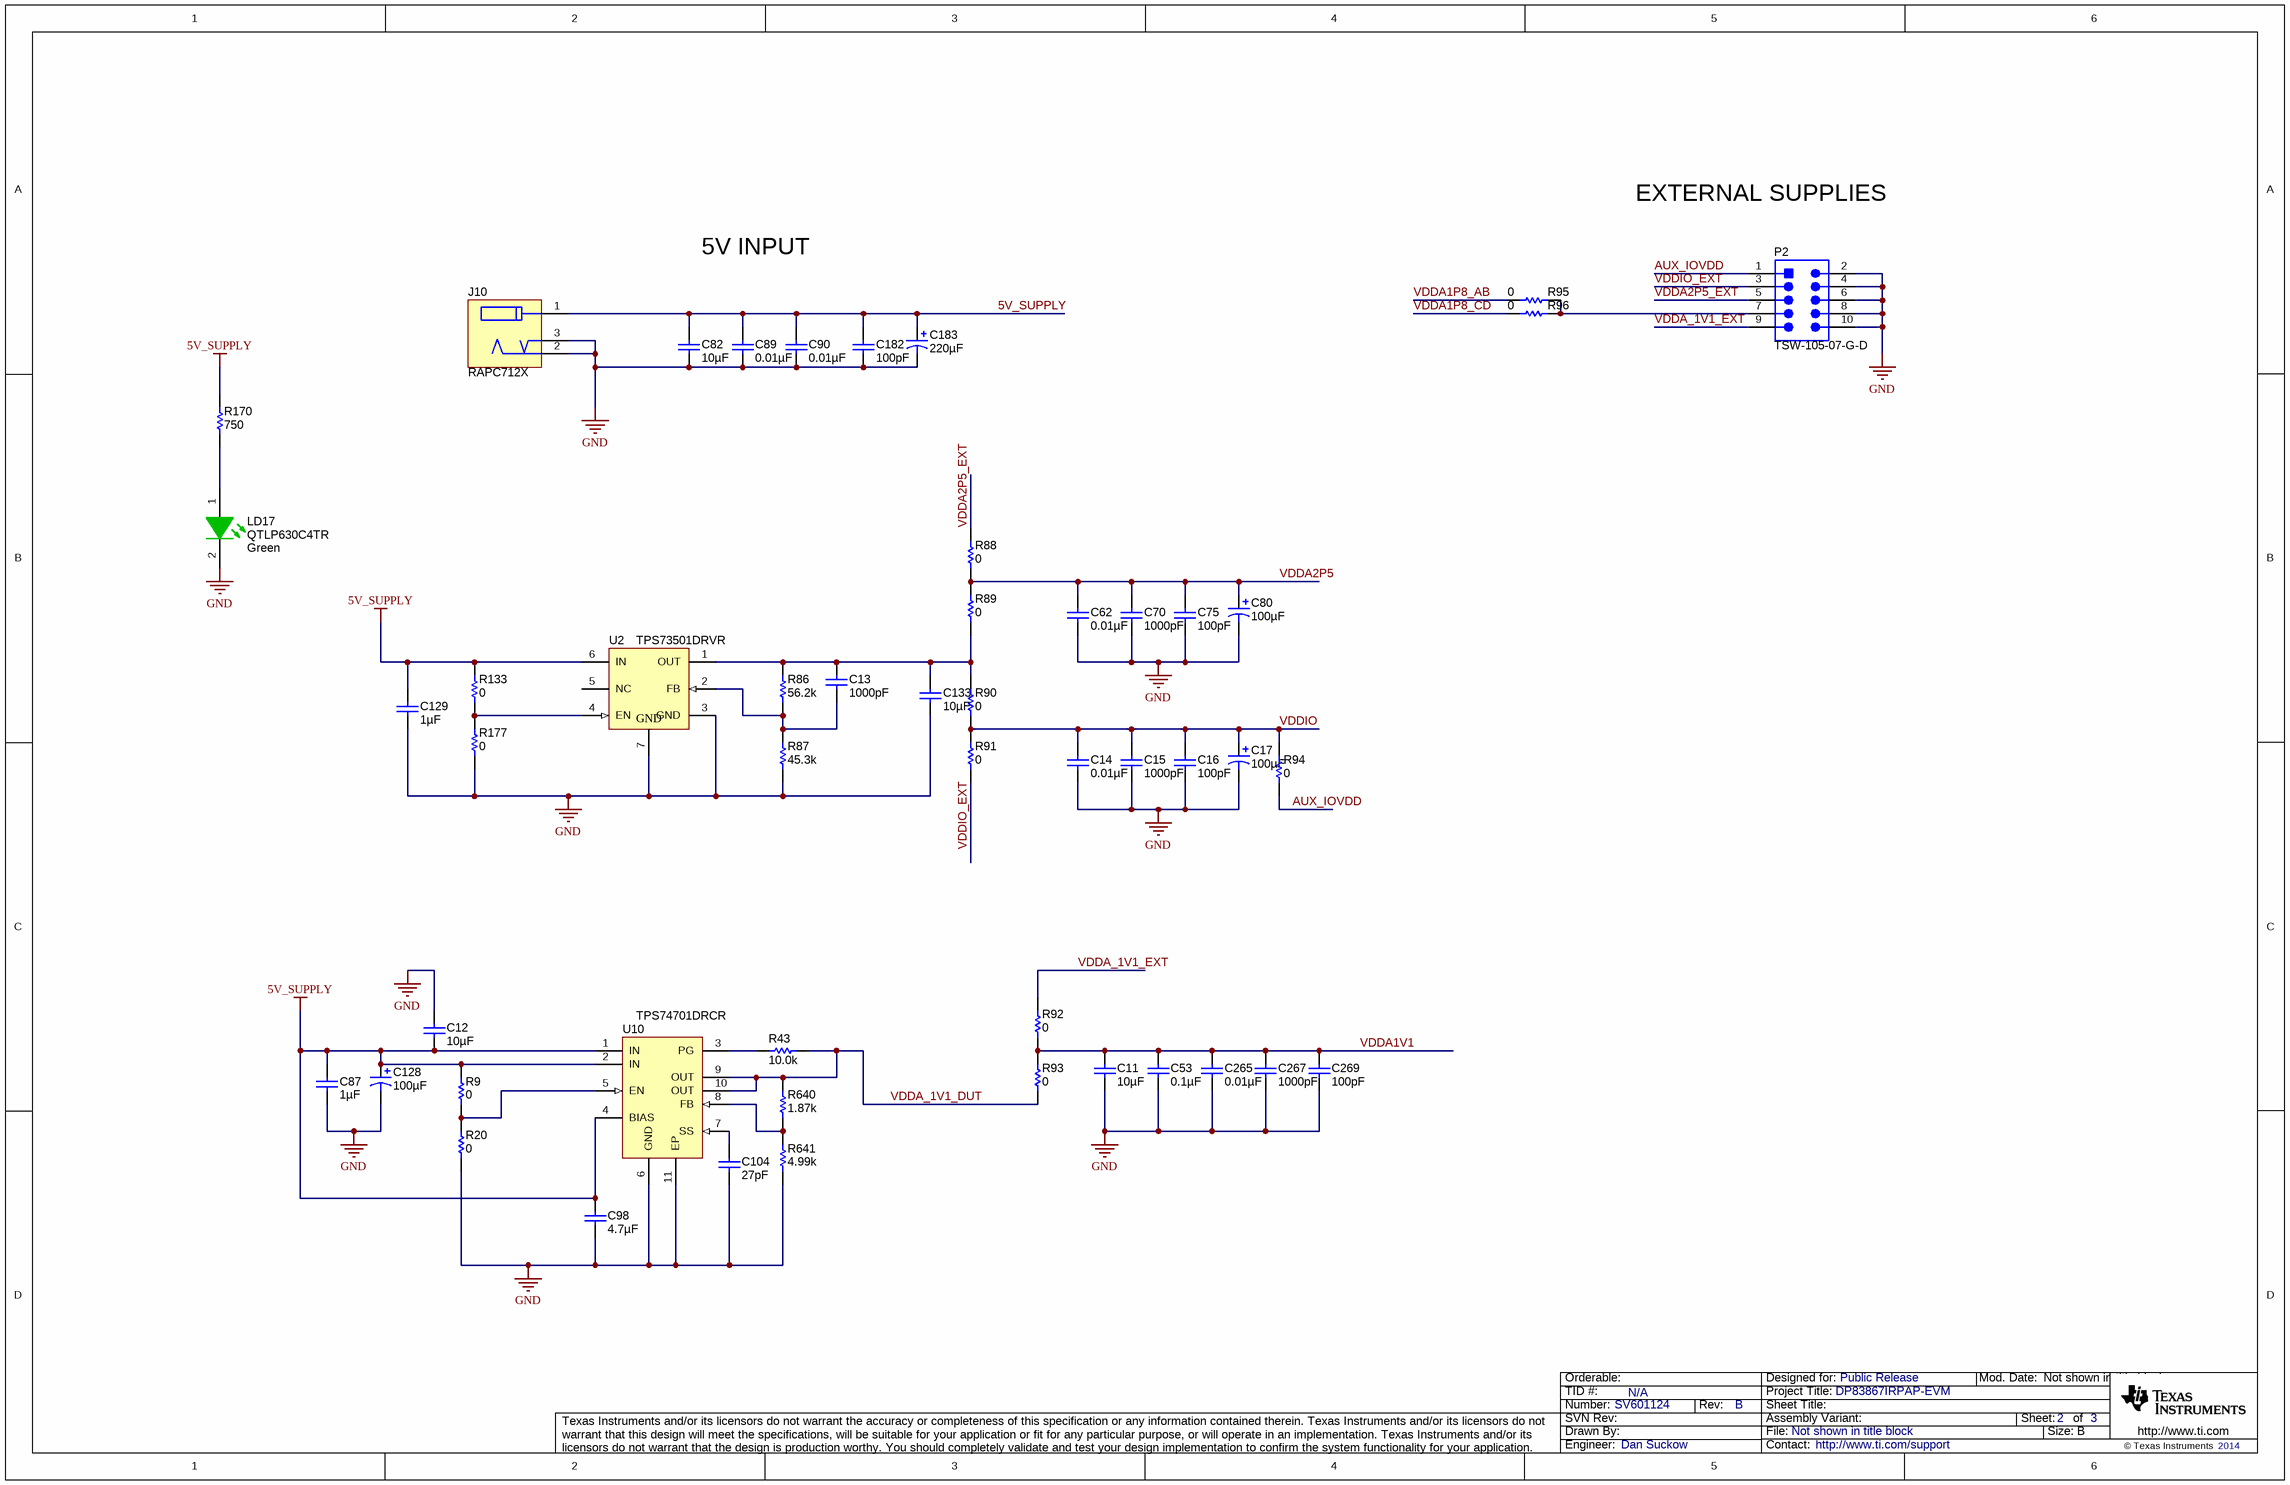
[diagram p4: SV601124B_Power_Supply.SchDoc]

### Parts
C11  ValueDisplayed: 10µF  [1206_190]  (hidden comment: C3216X7R1V106M160AC)
C12  ValueDisplayed: 10µF  [1206_190]  (hidden comment: C3216X7R1V106M160AC)
C13  ValueDisplayed: 1000pF  [0402]  (hidden comment: C0402C102J3RACTU)
C14  ValueDisplayed: 0.01µF  [0603]  (hidden comment: C0603C103J5RACTU)
C15  ValueDisplayed: 1000pF  [0603]  (hidden comment: 06035A102KAT2A)
C16  ValueDisplayed: 100pF  [0402]  (hidden comment: CC0402JRNPO9BN101)
C17  ValueDisplayed: 100µF  [7343-31]  (hidden comment: 593D107X0010D2TE3)
C53  ValueDisplayed: 0.1µF  [0603]  (hidden comment: CL10B104KO8NNNC)
C62  ValueDisplayed: 0.01µF  [0603]  (hidden comment: C0603C103J5RACTU)
C70  ValueDisplayed: 1000pF  [0603]  (hidden comment: 06035A102KAT2A)
C75  ValueDisplayed: 100pF  [0402]  (hidden comment: CC0402JRNPO9BN101)
C80  ValueDisplayed: 100µF  [7343-31]  (hidden comment: 593D107X0010D2TE3)
C82  ValueDisplayed: 10µF  [1206_190]  (hidden comment: C3216X7R1V106M160AC)
C87  ValueDisplayed: 1µF  [0805_HV]  (hidden comment: 0805YD105KAT2A)
C89  ValueDisplayed: 0.01µF  [0603]  (hidden comment: C0603C103J5RACTU)
C90  ValueDisplayed: 0.01µF  [0603]  (hidden comment: C0603C103J5RACTU)
C98  ValueDisplayed: 4.7µF  [0805_HV]  (hidden comment: CC0805ZRY5V6BB475)
C104  ValueDisplayed: 27pF  [0603L]  (hidden comment: CL10C270FB8NNNC)
C128  ValueDisplayed: 100µF  [7343-31]  (hidden comment: 593D107X0010D2TE3)
C129  ValueDisplayed: 1µF  [0603]  (hidden comment: CL10B105KQ8NNNC)
C133  ValueDisplayed: 10µF  [1206_190]  (hidden comment: C3216X7R1V106M160AC)
C182  ValueDisplayed: 100pF  [0402]  (hidden comment: CC0402JRNPO9BN101)
C183  ValueDisplayed: 220µF  [7343-31]  (hidden comment: T491D227K006AT)
C265  ValueDisplayed: 0.01µF  [0603]  (hidden comment: C0603C103J5RACTU)
C267  ValueDisplayed: 1000pF  [0603]  (hidden comment: 06035A102KAT2A)
C269  ValueDisplayed: 100pF  [0402]  (hidden comment: CC0402JRNPO9BN101)
J10  RAPC712X  [CONN_RAPC712X]
LD17  QTLP630C4TR  value Green  [QTLP630C_Green]
P2  TSW-105-07-G-D  [TSW-105-07-G-D]
R9  ValueDisplayed: 0  [0603]  (hidden comment: RC0603JR-070RL)
R20  ValueDisplayed: 0  [0603]  (hidden comment: RC0603JR-070RL)
R43  ValueDisplayed: 10.0k  [0603]  (hidden comment: RC0603FR-0710KL)
R86  ValueDisplayed: 56.2k  [0603]  (hidden comment: RC0603FR-0756K2L)
R87  ValueDisplayed: 45.3k  [0603]  (hidden comment: RC0603FR-0745K3L)
R88  ValueDisplayed: 0  [0603]  (hidden comment: RC0603JR-070RL)
R89  ValueDisplayed: 0  [0603]  (hidden comment: RC0603JR-070RL)
R90  ValueDisplayed: 0  [0603]  (hidden comment: RC0603JR-070RL)
R91  ValueDisplayed: 0  [0603]  (hidden comment: RC0603JR-070RL)
R92  ValueDisplayed: 0  [0603L]  (hidden comment: RC0603JR-070RL)
R93  ValueDisplayed: 0  [0603L]  (hidden comment: RC0603JR-070RL)
R94  ValueDisplayed: 0  [0603]  (hidden comment: RC0603JR-070RL)
R95  ValueDisplayed: 0  [0603]  (hidden comment: RC0603JR-070RL)
R96  ValueDisplayed: 0  [0603]  (hidden comment: RC0603JR-070RL)
R133  ValueDisplayed: 0  [0603]  (hidden comment: RC0603JR-070RL)
R170  ValueDisplayed: 750  [0603]  (hidden comment: RC0603JR-07750RL)
R177  ValueDisplayed: 0  [0603]  (hidden comment: RC0603JR-070RL)
R640  ValueDisplayed: 1.87k  [0603L]  (hidden comment: RC0603FR-071K87L)
R641  ValueDisplayed: 4.99k  [0603L]  (hidden comment: CPF0603B4K99E)
U2  TPS73501DRVR  [DRV0006A]
U10  TPS74701DRCR  [DRC0010A]

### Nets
5V_SUPPLY: C12.2 C82.1 C87.2 C89.2 C90.2 C98.1 C128.1(+) C129.2 C182.2 C183.1(+) J10.1 R9.2 R133.1 R170.2 U2.6(IN) U10.1(IN) U10.2(IN) U10.4(BIAS)
AUX_IOVDD: P2.1 R94.1
GND: C11.2 C12.1 C14.1 C15.1 C16.1 C17.2(-) C53.2 C62.1 C70.1 C75.1 C80.2(-) C82.2 C87.1 C89.1 C90.1 C98.2 C104.1 C128.2(-) C129.1 C133.2 C182.1 C183.2(-) C265.1 C267.1 C269.1 J10.2 J10.3 LD17.2(K) P2.2 P2.4 P2.6 P2.8 P2.10 R20.1 R87.1 R177.1 R641.1 U2.3(GND) U2.7(GND) U10.6(GND) U10.11(EP)
VDDA1P8_AB: R95.1
VDDA1P8_CD: R96.1
VDDA1V1: C11.1 C53.1 C265.2 C267.2 C269.2 R92.1 R93.2
VDDA2P5: C62.2 C70.2 C75.2 C80.1(+) R88.1 R89.2
VDDA2P5_EXT: P2.5 R88.2
VDDA_1V1_DUT: R43.1 R93.1 R640.2 U10.9(OUT) U10.10(OUT)
VDDA_1V1_EXT: P2.9 R92.2
VDDIO: C14.2 C15.2 C16.2 C17.1(+) R90.1 R91.2 R94.2
VDDIO_EXT: P2.3 R91.1
NetC13_1: C13.1 C133.1 R86.2 R89.1 R90.2 U2.1(OUT)
NetC13_2: C13.2 R86.1 R87.2 U2.2(FB)
NetC104_2: C104.2 U10.7(SS)
NetLD17_1: LD17.1(A) R170.1
NetP2_7: P2.7 R95.2 R96.2
NetR9_1: R9.1 R20.2 U10.5(EN)
NetR43_2: R43.2 U10.3(PG)
NetR133_2: R133.2 R177.2 U2.4(EN)
NetR640_1: R640.1 R641.2 U10.8(FB)

Not connected (* = marked no-connect by the designer): U2 5(NC)

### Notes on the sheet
- EXTERNAL SUPPLIES
- 5V INPUT

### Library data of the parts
C11 C12 C82 C133 = C3216X7R1V106M160AC: CAP, CERM, 10 µF, 35 V, +/- 20%, X7R, 1206_190; Manufacturer: TDK; Polarized: N; CompType: Capacitor; Value: 10uF; U/M: EA; Cap_F: 0.00001; Tolerance_%: 20; Value1: Unknown; VDC_V: 35; Value2: 35V; TaMin_C: -55; TaMax_C: 125; Cap_Case: 1206
C13 = C0402C102J3RACTU: as C271 on sheet SV601124B_DP83867IRPAP
C14 C62 C89 C90 C265 = C0603C103J5RACTU: CAP, CERM, 0.01 µF, 50 V, +/- 5%, X7R, 0603; Manufacturer: Kemet; Polarized: N; CompType: Capacitor; Value: 0.01uF; U/M: EA; Cap_F: 0.00000001; Tolerance_%: 5; Value1: Unknown; VDC_V: 50; Value2: 50V; TaMin_C: -55; TaMax_C: 125
C15 C70 C267 = 06035A102KAT2A: CAP, CERM, 1000 pF, 50 V, +/- 10%, C0G/NP0, 0603; Manufacturer: AVX; Polarized: N; CompType: Capacitor; Value: 1000pF; U/M: EA; Cap_F: 0.000000001; Tolerance_%: 10; ESR_ohm: 0.048; Value1: 0.048 ohm; VDC_V: 50; Value2: 50V; TaMin_C: -55; TaMax_C: 125
C16 C75 C182 C269 = CC0402JRNPO9BN101: as C272 on sheet SV601124B_DP83867IRPAP
C17 C80 C128 = 593D107X0010D2TE3: CAP, TA, 100 µF, 10 V, +/- 20%, 0.1 ohm, SMD; Manufacturer: Vishay-Sprague; Polarized: Y; CompType: Capacitor; Value: 100uF; U/M: EA; Cap_F: 0.0001; Tolerance_%: 20; Value1: 0.1 ohm; VDC_V: 10; Value2: 10V; ESR_ohm: 0.1; IRMS_A: 1.22; TaMin_C: -55; TaMax_C: 125; Cap_Case: D
C53 = CL10B104KO8NNNC: CAP, CERM, 0.1 µF, 16 V, +/- 10%, X7R, 0603; Manufacturer: Samsung; Polarized: N; CompType: Capacitor; Value: 0.1uF; U/M: EA; Cap_F: 0.0000001; Tolerance_%: 10; Value1: Unknown; VDC_V: 16; Value2: 16V; TaMin_C: -55; TaMax_C: 125
C87 = 0805YD105KAT2A: CAP, CERM, 1 µF, 16 V, +/- 10%, X5R, 0805; Manufacturer: AVX; Polarized: N; CompType: Capacitor; Value: 1uF; U/M: EA; Cap_F: 0.000001; Tolerance_%: 10; ESR_ohm: 0.012; Value1: 0.012 ohm; VDC_V: 16; Value2: 16V; TaMin_C: -55; TaMax_C: 85; Cap_Case: 0805
C98 = CC0805ZRY5V6BB475: CAP, CERM, 4.7 µF, 10 V, +80/-20%, Y5V, 0805; Manufacturer: Yageo America; Polarized: N; CompType: Capacitor; Value: 4.7uF; U/M: EA; Cap_F: 0.0000047; Tolerance_%: 80; Value1: Unknown; VDC_V: 10; Value2: 10V; TaMin_C: -30; TaMax_C: 85; Cap_Case: 0805
C104 = CL10C270FB8NNNC: CAP, CERM, 27 pF, 50 V, +/- 1%, C0G/NP0, 0603; Manufacturer: Samsung; Polarized: N; CompType: Capacitor; Value: 27pF; U/M: EA; Cap_F: 0.000000000027; Tolerance_%: 1; Value1: Unknown; VDC_V: 50; Value2: 50V; TaMin_C: -55; TaMax_C: 125; Cap_Case: 0603
C129 = CL10B105KQ8NNNC: CAP, CERM, 1 µF, 6.3 V, +/- 10%, X7R, 0603; Manufacturer: Samsung; Polarized: N; CompType: Capacitor; Value: 1uF; U/M: EA; Cap_F: 0.000001; Tolerance_%: 10; Value1: Unknown; VDC_V: 6.3; Value2: 6.3V; TaMin_C: -55; TaMax_C: 125
C183 = T491D227K006AT: CAP, TA, 220 µF, 6.3 V, +/- 10%, 0.7 ohm, SMD; Manufacturer: Kemet; Polarized: Y; CompType: Capacitor; Value: 220uF; U/M: EA; Cap_F: 0.00022; Tolerance_%: 10; Value1: 0.7 ohm; VDC_V: 6.3; Value2: 6.3V; ESR_ohm: 0.7; IRMS_A: 0.463; TaMin_C: -55; TaMax_C: 125; Cap_Case: D
J10 = RAPC712X: Power Jack, mini, 2.5mm OD, R/A, TH; Manufacturer: Switchcraft; SymbolCreator: a0799628; U/M: EA
LD17 = QTLP630C4TR: LED, Green, SMD; Manufacturer: Everlight; SymbolCreator: Altium; Vf_V: 2.1; Value2: 2.1V; Io_A: 0.02; Vr_V: 5; Tjmax_C: 85; Value1: W; Angle: 140; U/M: EA
P2 = TSW-105-07-G-D: as P1 on sheet SV601124B_DP83867IRPAP
R9 R20 R88-R96 R133 R177 = RC0603JR-070RL: as R22 on sheet SV601124B_Block_Diagram
R43 = RC0603FR-0710KL: RES, 10.0 k, 1%, 0.1 W, 0603; Manufacturer: Yageo America; CompType: Resistor; Value: 10.0k; Res_ohm: 10000; Value_Code: 10k0; Tolerance_%: 1; Power_W: 0.1; Value2: 0.1W; VDC_V: 150; TempCo: 200 ppm/C; EIA_Code: E96; U/M: EA
R86 = RC0603FR-0756K2L: RES, 56.2 k, 1%, 0.1 W, 0603; Manufacturer: Yageo America; CompType: Resistor; Value: 56.2k; Res_ohm: 56200; Value_Code: 56k2; Tolerance_%: 1; Power_W: 0.1; Value2: 0.1W; VDC_V: 150; TempCo: 200 ppm/C; EIA_Code: E96; U/M: EA
R87 = RC0603FR-0745K3L: RES, 45.3 k, 1%, 0.1 W, 0603; Manufacturer: Yageo America; CompType: Resistor; Value: 45.3k; Res_ohm: 45300; Value_Code: 45k3; Tolerance_%: 1; Power_W: 0.1; Value2: 0.1W; VDC_V: 150; TempCo: 200 ppm/C; EIA_Code: E96; U/M: EA
R170 = RC0603JR-07750RL: RES, 750, 5%, 0.1 W, 0603; Manufacturer: Yageo America; CompType: Resistor; Value: 750; Value_Code: 750R; Tolerance_%: 5; Power_W: 0.1; Value2: 0.1W; VDC_V: 50; TempCo: 100 ppm/C; EIA_Code: E24; U/M: EA
R640 = RC0603FR-071K87L: RES, 1.87 k, 1%, 0.1 W, 0603; Manufacturer: Yageo America; CompType: Resistor; Value: 1.87k; Res_ohm: 1870; Value_Code: 1k87; Tolerance_%: 1; Power_W: 0.1; Value2: 0.1W; VDC_V: 150; TempCo: 200 ppm/C; EIA_Code: E96; U/M: EA
R641 = CPF0603B4K99E: RES, 4.99 k, 0.1%, 0.063 W, 0603; Manufacturer: TE Connectivity; CompType: Resistor; Value: 4.99k; Res_ohm: 4990; Value_Code: 4k99; Tolerance_%: 0.1; Power_W: 0.063; Value2: 0.063W; VDC_V: 50; TempCo: 25 ppm/C; EIA_Code: E192; U/M: EA
U2 = TPS73501DRVR: Single Output High PSRR LDO, 500 mA, Adjustable 1.25 to 6 V Output, 2.7 to 6.5 V Input, with Low IQ, 6-pin SON (DRV), -40 to 125 degC, Green (RoHS & no Sb/Br); Manufacturer: Texas Instruments; Alternate Manufacturer: None; Alternate PartNumber: Equivalent; Accuracy(%): 2; Iout(Max)(A): 0.5; Iq(Typ)(mA): 0.04; SubFamily: Single Channel LDO; Vdo(Typ)(mV): 280; Vin(Max)(V): 6.5; Vin(Min)(V): 2.7; Vout Adj(Max)(V): 6; Vout Adj(Min)(V): 1.25
U10 = TPS74701DRCR: Single Output LDO, 500 mA, Adjustable 0.8 to 3.6 V Output, 0.8 to 5.5 V Input, with Programmable Soft Start, 10-pin SON (DRC), -40 to 125 degC, Green (RoHS & no Sb/Br); Manufacturer: Texas Instruments; Alternate Manufacturer: None; Alternate PartNumber: Equivalent; Accuracy(%): 2; Iout(Max)(A): 0.5; Iq(Typ)(mA): 1; Power Good: TRUE; Rating: Catalog; SubFamily: Single Channel LDO; Vdo(Typ)(mV): 50; Vin(Max)(V): 5.5; Vin(Min)(V): 0.8; Vout Adj(Max)(V): 3.6

## Sheet SV601124B_Configuration pins.SchDoc
size 431 x 279 mm; Date: Not shown in title block; ApprovedBy: Not shown in title block; CheckedBy: Not shown in title block; Author: Not shown in title block; CompanyName: Not shown in title block; Engineer: Not shown in title block; Organization: Not shown in title block; Address1: Not shown in title block; Address2: Not shown in title block; Address3: Not shown in title block; Address4: Not shown in title block; DocumentNumber: 1; Revision: Use project parameter SCH_Rev; SheetNumber: 2; SheetTotal: 3; PageSetup: Record=PageOptions¦CenterHorizontal=True¦CenterVertical=True¦PrintScale=1.00¦XCorrection=1.00¦YCorrection=1.00¦PrintKind=0¦BorderSize=5000000¦LeftOffset=0¦BottomOffset=0¦Orientation=2¦PaperLength=1000¦PaperWidth=1000¦Scale=100¦PaperSource=15¦PrintQuality=600¦MediaType=1¦DitherType=10¦PaperKind=Letter¦PrintScaleMode=1
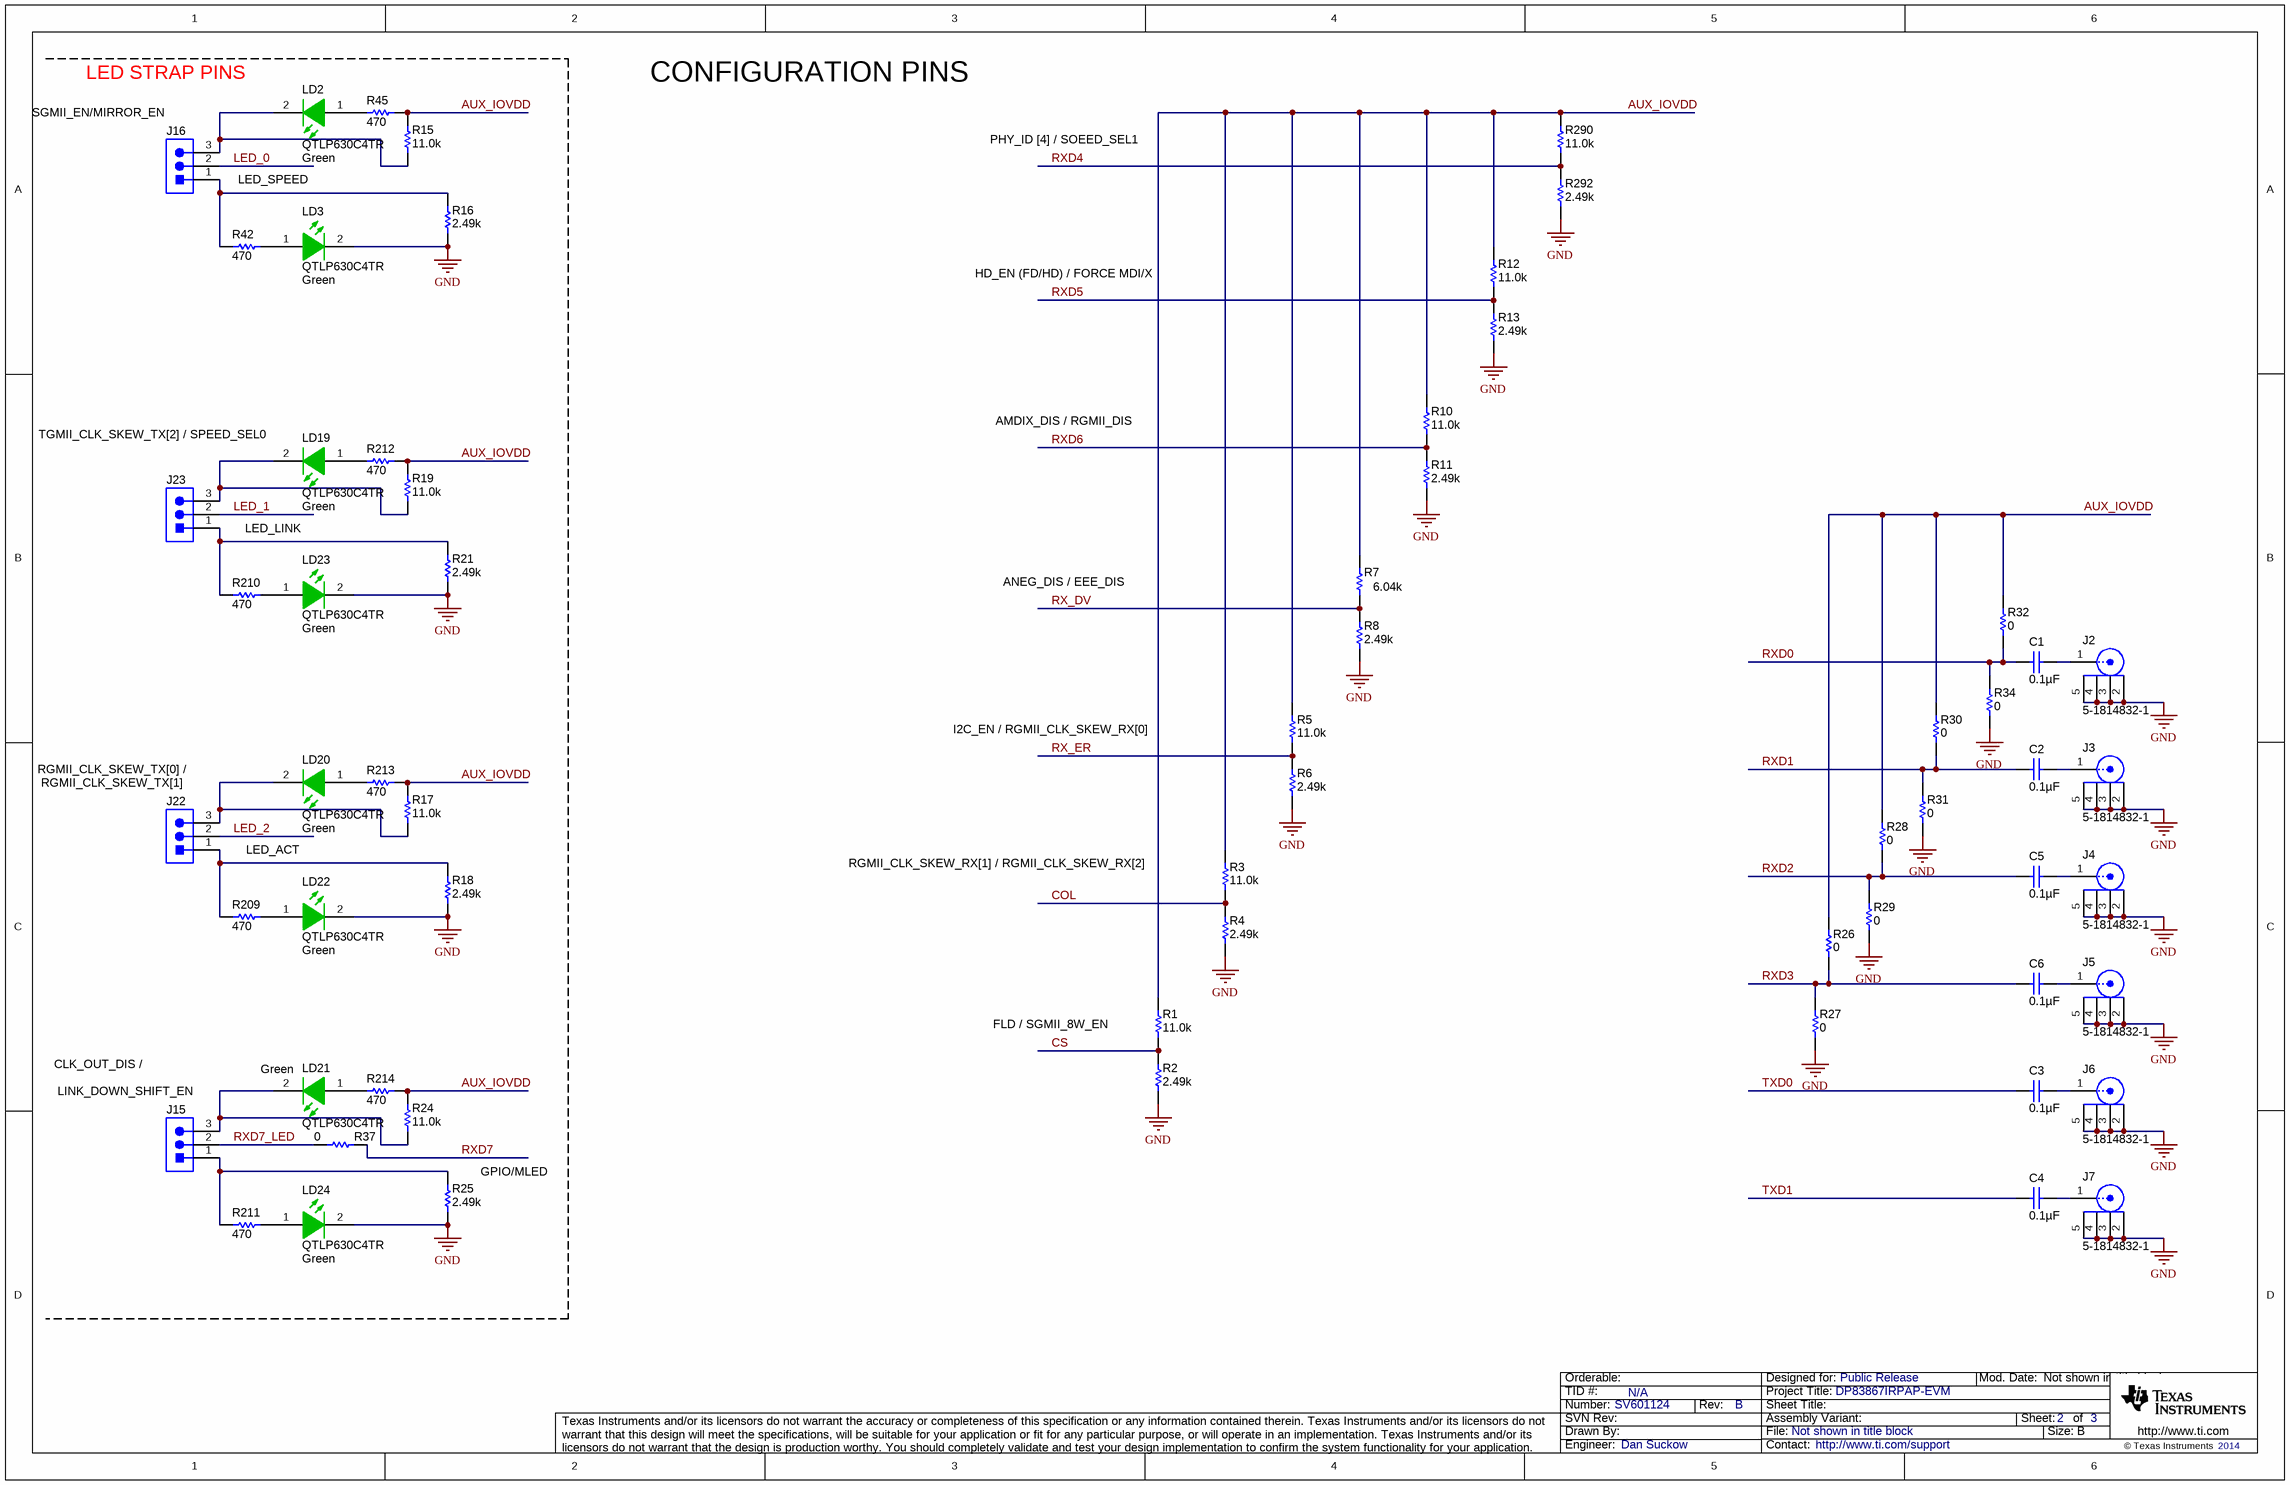
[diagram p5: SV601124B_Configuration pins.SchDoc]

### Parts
C1  ValueDisplayed: 0.1µF  [0201L]  (hidden comment: C0603X5R0J104K030BC)
C2  ValueDisplayed: 0.1µF  [0201L]  (hidden comment: C0603X5R0J104K030BC)
C3  ValueDisplayed: 0.1µF  [0201L]  (hidden comment: C0603X5R0J104K030BC)
C4  ValueDisplayed: 0.1µF  [0201L]  (hidden comment: C0603X5R0J104K030BC)
C5  ValueDisplayed: 0.1µF  [0201L]  (hidden comment: C0603X5R0J104K030BC)
C6  ValueDisplayed: 0.1µF  [0201L]  (hidden comment: C0603X5R0J104K030BC)
J2  5-1814832-1  [TE_5-1814832-1]
J3  5-1814832-1  [TE_5-1814832-1]
J4  5-1814832-1  [TE_5-1814832-1]
J5  5-1814832-1  [TE_5-1814832-1]
J6  5-1814832-1  [TE_5-1814832-1]
J7  5-1814832-1  [TE_5-1814832-1]
J15  TSW-103-07-G-S  [TSW-103-07-G-S]  (value not drawn)
J16  TSW-103-07-G-S  [TSW-103-07-G-S]  (value not drawn)
J22  TSW-103-07-G-S  [TSW-103-07-G-S]  (value not drawn)
J23  TSW-103-07-G-S  [TSW-103-07-G-S]  (value not drawn)
LD2  QTLP630C4TR  value Green  [QTLP630C_Green]
LD3  QTLP630C4TR  value Green  [QTLP630C_Green]
LD19  QTLP630C4TR  value Green  [QTLP630C_Green]
LD20  QTLP630C4TR  value Green  [QTLP630C_Green]
LD21  QTLP630C4TR  value Green  [QTLP630C_Green]
LD22  QTLP630C4TR  value Green  [QTLP630C_Green]
LD23  QTLP630C4TR  value Green  [QTLP630C_Green]
LD24  QTLP630C4TR  value Green  [QTLP630C_Green]
R1  ValueDisplayed: 11.0k  [0603]  (hidden comment: RC0603FR-0711KL)
R2  ValueDisplayed: 2.49k  [0603]  (hidden comment: RC0603FR-072K49L)
R3  ValueDisplayed: 11.0k  [0603L]  (hidden comment: RC0603FR-0711KL)
R4  ValueDisplayed: 2.49k  [0603L]  (hidden comment: RC0603FR-072K49L)
R5  ValueDisplayed: 11.0k  [0603L]  (hidden comment: RC0603FR-0711KL)
R6  ValueDisplayed: 2.49k  [0603L]  (hidden comment: RC0603FR-072K49L)
R7  ValueDisplayed: 6.04k  [0603L]  (hidden comment: RC0603FR-076K04L)
R8  ValueDisplayed: 2.49k  [0603]  (hidden comment: RC0603FR-072K49L)
R10  ValueDisplayed: 11.0k  [0603]  (hidden comment: RC0603FR-0711KL)
R11  ValueDisplayed: 2.49k  [0603L]  (hidden comment: RC0603FR-072K49L)
R12  ValueDisplayed: 11.0k  [0603]  (hidden comment: RC0603FR-0711KL)
R13  ValueDisplayed: 2.49k  [0603]  (hidden comment: RC0603FR-072K49L)
R15  ValueDisplayed: 11.0k  [0603]  (hidden comment: RC0603FR-0711KL)
R16  ValueDisplayed: 2.49k  [0603L]  (hidden comment: RC0603FR-072K49L)
R17  ValueDisplayed: 11.0k  [0603]  (hidden comment: RC0603FR-0711KL)
R18  ValueDisplayed: 2.49k  [0603]  (hidden comment: RC0603FR-072K49L)
R19  ValueDisplayed: 11.0k  [0603]  (hidden comment: RC0603FR-0711KL)
R21  ValueDisplayed: 2.49k  [0603]  (hidden comment: RC0603FR-072K49L)
R24  ValueDisplayed: 11.0k  [0603]  (hidden comment: RC0603FR-0711KL)
R25  ValueDisplayed: 2.49k  [0603]  (hidden comment: RC0603FR-072K49L)
R26  ValueDisplayed: 0  [0201L]  (hidden comment: ERJ-1GE0R00C)
R27  ValueDisplayed: 0  [0201L]  (hidden comment: ERJ-1GE0R00C)
R28  ValueDisplayed: 0  [0201L]  (hidden comment: ERJ-1GE0R00C)
R29  ValueDisplayed: 0  [0201L]  (hidden comment: ERJ-1GE0R00C)
R30  ValueDisplayed: 0  [0201L]  (hidden comment: ERJ-1GE0R00C)
R31  ValueDisplayed: 0  [0201L]  (hidden comment: ERJ-1GE0R00C)
R32  ValueDisplayed: 0  [0201L]  (hidden comment: ERJ-1GE0R00C)
R34  ValueDisplayed: 0  [0201L]  (hidden comment: ERJ-1GE0R00C)
R37  ValueDisplayed: 0  [0402L]  (hidden comment: CRCW04020000Z0ED)
R42  ValueDisplayed: 470  [0603]  (hidden comment: RC0603FR-07470RL)
R45  ValueDisplayed: 470  [0603]  (hidden comment: RC0603FR-07470RL)
R209  ValueDisplayed: 470  [0603]  (hidden comment: RC0603FR-07470RL)
R210  ValueDisplayed: 470  [0603]  (hidden comment: RC0603FR-07470RL)
R211  ValueDisplayed: 470  [0603]  (hidden comment: RC0603FR-07470RL)
R212  ValueDisplayed: 470  [0603]  (hidden comment: RC0603FR-07470RL)
R213  ValueDisplayed: 470  [0603]  (hidden comment: RC0603FR-07470RL)
R214  ValueDisplayed: 470  [0603]  (hidden comment: RC0603FR-07470RL)
R290  ValueDisplayed: 11.0k  [0603]  (hidden comment: RC0603FR-0711KL)
R292  ValueDisplayed: 2.49k  [0603]  (hidden comment: RC0603FR-072K49L)

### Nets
AUX_IOVDD: R1.2 R3.2 R5.2 R7.2 R10.2 R12.2 R15.2 R17.2 R19.2 R24.2 R26.2 R28.2 R30.2 R32.2 R45.1 R212.1 R213.1 R214.2 R290.2
GND: J2.2 J2.3 J2.4 J2.5 J3.2 J3.3 J3.4 J3.5 J4.2 J4.3 J4.4 J4.5 J5.2 J5.3 J5.4 J5.5 J6.2 J6.3 J6.4 J6.5 J7.2 J7.3 J7.4 J7.5 LD3.2(K) LD22.2(K) LD23.2(K) LD24.2(K) R2.1 R4.1 R6.1 R8.1 R11.1 R13.1 R16.1 R18.1 R21.1 R25.1 R27.1 R29.1 R31.1 R34.1 R292.1
COL: R3.1 R4.2
CS: R1.1 R2.2
LED_0: J16.2
LED_1: J23.2
LED_2: J22.2
RX_DV: R7.1 R8.2
RX_ER: R5.1 R6.2
RXD0: C1.2 R32.1 R34.2
RXD1: C2.2 R30.1 R31.2
RXD2: C5.2 R28.1 R29.2
RXD3: C6.2 R26.1 R27.2
RXD4: R290.1 R292.2
RXD5: R12.1 R13.2
RXD6: R10.1 R11.2
RXD7: R37.1
RXD7_LED: J15.2 R37.2
TXD0: C3.2
TXD1: C4.2
NetC1_1: C1.1 J2.1
NetC2_1: C2.1 J3.1
NetC3_1: C3.1 J6.1
NetC4_1: C4.1 J7.1
NetC5_1: C5.1 J4.1
NetC6_1: C6.1 J5.1
NetJ15_1: J15.1 R25.2 R211.1
NetJ15_3: J15.3 LD21.2(K) R24.1
NetJ16_1: J16.1 R16.2 R42.1
NetJ16_3: J16.3 LD2.2(K) R15.1
NetJ22_1: J22.1 R18.2 R209.1
NetJ22_3: J22.3 LD20.2(K) R17.1
NetJ23_1: J23.1 R21.2 R210.1
NetJ23_3: J23.3 LD19.2(K) R19.1
NetLD2_1: LD2.1(A) R45.2
NetLD3_1: LD3.1(A) R42.2
NetLD19_1: LD19.1(A) R212.2
NetLD20_1: LD20.1(A) R213.2
NetLD21_1: LD21.1(A) R214.1
NetLD22_1: LD22.1(A) R209.2
NetLD23_1: LD23.1(A) R210.2
NetLD24_1: LD24.1(A) R211.2

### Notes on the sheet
- LED STRAP PINS
- CONFIGURATION PINS
- (near J16) SGMII_EN/MIRROR_EN
- PHY_ID [4] / SOEED_SEL1
- LED_SPEED
- HD_EN (FD/HD) / FORCE MDI/X
- TGMII_CLK_SKEW_TX[2] / SPEED_SEL0
- AMDIX_DIS / RGMII_DIS
- LED_LINK
- ANEG_DIS / EEE_DIS
- (near J22) RGMII_CLK_SKEW_TX[0] /
- I2C_EN / RGMII_CLK_SKEW_RX[0]
- (near J22) RGMII_CLK_SKEW_TX[1]
- LED_ACT
- RGMII_CLK_SKEW_RX[1] / RGMII_CLK_SKEW_RX[2]
- FLD / SGMII_8W_EN
- CLK_OUT_DIS /
- (near J15) LINK_DOWN_SHIFT_EN
- (near R25) GPIO/MLED

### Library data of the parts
C1-C6 = C0603X5R0J104K030BC: CAP, CERM, 0.1 µF, 6.3 V, +/- 10%, X5R, 0201; Manufacturer: TDK; Polarized: N; CompType: Capacitor; Value: 0.1uF; U/M: EA; Cap_F: 0.0000001; Tolerance_%: 10; Value1: Unknown; VDC_V: 6.3; Value2: 6.3V; TaMin_C: -55; TaMax_C: 85; Cap_Case: 0201
J2-J7 = 5-1814832-1: SMA Straight PCB Socket Die Cast, 50 Ohm, TH; Manufacturer: TE Connectivity; SymbolCreator: X0208326; CompType: JACK; U/M: EA
J15 J16 J22 J23 = TSW-103-07-G-S: Header, 100mil, 3x1, Gold, TH; Manufacturer: Samtec; SymbolCreator: a0799628; U/M: EA
LD2 LD3 LD19-LD24 = QTLP630C4TR: as LD17 on sheet SV601124B_Power_Supply
R1 R3 R5 R10 R12 R15 R17 R19 R24 R290 = RC0603FR-0711KL: RES, 11.0 k, 1%, 0.1 W, 0603; Manufacturer: Yageo America; CompType: Resistor; Value: 11.0k; Res_ohm: 11000; Value_Code: 11k0; Tolerance_%: 1; Power_W: 0.1; Value2: 0.1W; VDC_V: 150; TempCo: 200 ppm/C; EIA_Code: E96; U/M: EA
R2 R4 R6 R8 R11 R13 R16 R18 R21 R25 R292 = RC0603FR-072K49L: RES, 2.49 k, 1%, 0.1 W, 0603; Manufacturer: Yageo America; CompType: Resistor; Value: 2.49k; Res_ohm: 2490; Value_Code: 2k49; Tolerance_%: 1; Power_W: 0.1; Value2: 0.1W; VDC_V: 150; TempCo: 200 ppm/C; EIA_Code: E96; U/M: EA
R7 = RC0603FR-076K04L: RES, 6.04 k, 1%, 0.1 W, 0603; Manufacturer: Yageo America; CompType: Resistor; Value: 6.04k; Res_ohm: 6040; Value_Code: 6k04; Tolerance_%: 1; Power_W: 0.1; Value2: 0.1W; VDC_V: 150; TempCo: 200 ppm/C; EIA_Code: E96; U/M: EA
R26-R32 R34 = ERJ-1GE0R00C: as R51 on sheet SV601124B_Block_Diagram
R37 = CRCW04020000Z0ED: as R35 on sheet SV601124B_Block_Diagram
R42 R45 R209-R214 = RC0603FR-07470RL: RES, 470, 1%, 0.1 W, 0603; Manufacturer: Yageo America; CompType: Resistor; Value: 470; Value_Code: 470R; Tolerance_%: 1; Power_W: 0.1; Value2: 0.1W; VDC_V: 150; TempCo: 200 ppm/C; U/M: EA

## Sheet SV601124B_Magnetics.SchDoc
size 431 x 279 mm; Date: Not shown in title block; ApprovedBy: Not shown in title block; CheckedBy: Not shown in title block; Author: Not shown in title block; CompanyName: Not shown in title block; Engineer: Not shown in title block; Organization: Not shown in title block; Address1: Not shown in title block; Address2: Not shown in title block; Address3: Not shown in title block; Address4: Not shown in title block; DocumentNumber: 1; Revision: Use project parameter SCH_Rev; SheetNumber: 2; SheetTotal: 3; PageSetup: Record=PageOptions¦CenterHorizontal=True¦CenterVertical=True¦PrintScale=1.00¦XCorrection=1.00¦YCorrection=1.00¦PrintKind=0¦BorderSize=5000000¦LeftOffset=0¦BottomOffset=0¦Orientation=2¦PaperLength=1000¦PaperWidth=1000¦Scale=100¦PaperSource=15¦PrintQuality=600¦MediaType=1¦DitherType=10¦PaperKind=Letter¦PrintScaleMode=1
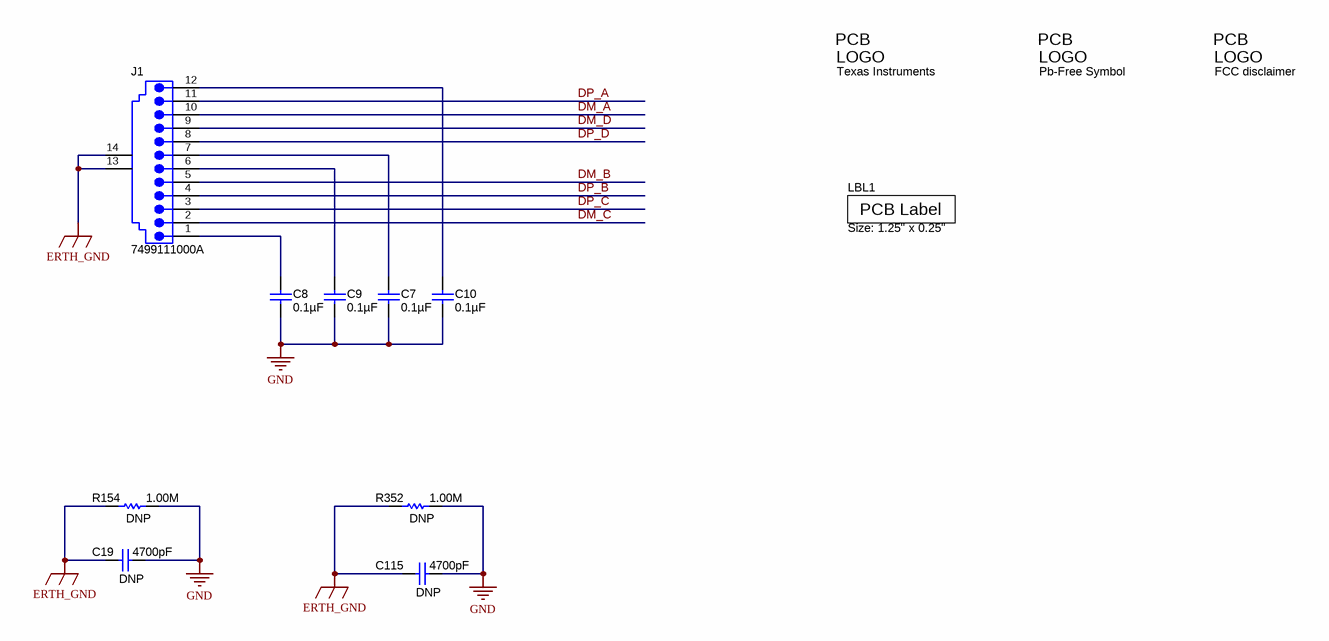
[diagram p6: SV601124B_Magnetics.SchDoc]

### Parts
C7  ValueDisplayed: 0.1µF  [0603]  (hidden comment: CL10B104KO8NNNC)
C8  ValueDisplayed: 0.1µF  [0603]  (hidden comment: CL10B104KO8NNNC)
C9  ValueDisplayed: 0.1µF  [0603]  (hidden comment: CL10B104KO8NNNC)
C10  ValueDisplayed: 0.1µF  [0603]  (hidden comment: CL10B104KO8NNNC)
C19  DNP  ValueDisplayed: 4700pF  [1812_254]
C115  DNP  ValueDisplayed: 4700pF  [1812_254]
J1  7499111000A  [Wurth_7499111000A]
LBL1  Size: 1.25" x 0.25"  [Label_1250x250]
Logo1  Texas Instruments  [TI_Horizontal_Overlay_Medium]  (no BOM)
Logo2  Pb-Free Symbol  [Pb-Free_Overlay_Medium]  (no BOM)
Logo3  FCC disclaimer  [FCC_disclaimer]  (no BOM)
R154  DNP  ValueDisplayed: 1.00M  [0402]
R352  DNP  ValueDisplayed: 1.00M  [0402]

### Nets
ERTH_GND: C19.2 C115.2 J1.13 J1.14 R154.1 R352.1
GND: C7.2 C8.2 C9.2 C10.2 C19.1 C115.1 R154.2 R352.2
DM_A: J1.10
DM_B: J1.5
DM_C: J1.2
DM_D: J1.9
DP_A: J1.11
DP_B: J1.4
DP_C: J1.3
DP_D: J1.8
NetC7_1: C7.1 J1.7
NetC8_1: C8.1 J1.1
NetC9_1: C9.1 J1.6
NetC10_1: C10.1 J1.12

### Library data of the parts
C7-C10 = CL10B104KO8NNNC: as C53 on sheet SV601124B_Power_Supply
C19 C115 = 1812GC472KAT1A: CAP, CERM, 4700 pF, 2000 V, +/- 10%, X7R, 1812; Manufacturer: AVX; Polarized: N; CompType: Capacitor; Value: 4700pF; U/M: EA; Cap_F: 0.0000000047; Tolerance_%: 10; Value1: Unknown; VDC_V: 2000; Value2: 2000V; TaMin_C: -55; TaMax_C: 125; Cap_Case: 1812
J1 = 7499111000A: RJ45, Gold, R/A, TH; Manufacturer: Wurth Elektronik eiSos; SymbolCreator: Altium; CompType: JACK; U/M: EA
LBL1 = THT-13-457-10: Thermal Transfer Printable Labels, 1.250" W x 0.250" H - 10,000 per roll; Manufacturer: Brady; SymbolCreator: a0412235; CompType: Label
Logo1 = TI_Logo: Texas Instrument Corporate Signature; SymbolCreator: a0412235
Logo2 = Pb-Free: SymbolCreator: a0412235
Logo3 = FCC_disclaimer: SymbolCreator: codlsc
R154 R352 = RC0402FR-071ML: as R652 on sheet SV601124B_DP83867IRPAP

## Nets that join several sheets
AUX_IOVDD: SV601124B_DP83867IRPAP (12 pins), SV601124B_Power_Supply (P2.1 R94.1), SV601124B_Configuration pins (19 pins)
ERTH_GND: SV601124B_Block_Diagram (M203.1), SV601124B_Magnetics (6 pins)
GND: SV601124B_Block_Diagram (57 pins), SV601124B_DP83867IRPAP (27 pins), SV601124B_Power_Supply (41 pins), SV601124B_Configuration pins (43 pins), SV601124B_Magnetics (8 pins)
ATP_16: SV601124B_Block_Diagram (R38.2), SV601124B_DP83867IRPAP (U1.16)
CLKOUT: SV601124B_Block_Diagram (J8.29 R82.2), SV601124B_DP83867IRPAP (U1.22)
COL: SV601124B_Block_Diagram (J9.3 R55.1), SV601124B_DP83867IRPAP (U1.55), SV601124B_Configuration pins (R3.1 R4.2)
CS: SV601124B_Block_Diagram (J9.1 R46.1), SV601124B_DP83867IRPAP (U1.56), SV601124B_Configuration pins (R1.1 R2.2)
DM_A: SV601124B_DP83867IRPAP (U1.3), SV601124B_Magnetics (J1.10)
DM_B: SV601124B_DP83867IRPAP (U1.6), SV601124B_Magnetics (J1.5)
DM_C: SV601124B_DP83867IRPAP (U1.11), SV601124B_Magnetics (J1.2)
DM_D: SV601124B_DP83867IRPAP (U1.14), SV601124B_Magnetics (J1.9)
DP_A: SV601124B_DP83867IRPAP (U1.2), SV601124B_Magnetics (J1.11)
DP_B: SV601124B_DP83867IRPAP (U1.5), SV601124B_Magnetics (J1.4)
DP_C: SV601124B_DP83867IRPAP (U1.10), SV601124B_Magnetics (J1.3)
DP_D: SV601124B_DP83867IRPAP (U1.13), SV601124B_Magnetics (J1.8)
EXT_REF_CLK: SV601124B_Block_Diagram (R78.1), SV601124B_DP83867IRPAP (R98.1)
GTX_CLK: SV601124B_Block_Diagram (J8.5 R100.1), SV601124B_DP83867IRPAP (U1.40)
INT_PWDN: SV601124B_Block_Diagram (J9.27 R39.2), SV601124B_DP83867IRPAP (R14.1 U1.60)
JTAG_CLK: SV601124B_Block_Diagram (R104.2), SV601124B_DP83867IRPAP (P1.6 R922.2 U1.25)
JTAG_TDI: SV601124B_Block_Diagram (R109.2), SV601124B_DP83867IRPAP (P1.10 R924.2 U1.28)
JTAG_TDO: SV601124B_Block_Diagram (R103.2), SV601124B_DP83867IRPAP (P1.8 R923.2 U1.26)
JTAG_TMS: SV601124B_Block_Diagram (R110.2), SV601124B_DP83867IRPAP (P1.4 R921.2 U1.27)
JTAG_TRSTN: SV601124B_Block_Diagram (R106.2), SV601124B_DP83867IRPAP (P1.2 R36.1 R920.2)
LED_0: SV601124B_Block_Diagram (J9.29 R41.1), SV601124B_DP83867IRPAP (U1.63), SV601124B_Configuration pins (J16.2)
LED_1: SV601124B_Block_Diagram (J9.31 R44.1), SV601124B_DP83867IRPAP (U1.62), SV601124B_Configuration pins (J23.2)
LED_2: SV601124B_Block_Diagram (J9.33 R40.1), SV601124B_DP83867IRPAP (U1.61), SV601124B_Configuration pins (J22.2)
MDC: SV601124B_Block_Diagram (R73.1 R108.2), SV601124B_DP83867IRPAP (U1.20)
MDIO: SV601124B_Block_Diagram (R77.1 R107.2), SV601124B_DP83867IRPAP (R651.2 U1.21)
RESET_N: SV601124B_Block_Diagram (R35.1), SV601124B_DP83867IRPAP (C318.2 J12.1 U1.59)
RX_CLK: SV601124B_Block_Diagram (J9.25 R60.1), SV601124B_DP83867IRPAP (U1.43)
RX_DV: SV601124B_Block_Diagram (J9.7 R53.2), SV601124B_DP83867IRPAP (U1.53), SV601124B_Configuration pins (R7.1 R8.2)
RX_ER: SV601124B_Block_Diagram (J9.5 R71.2), SV601124B_DP83867IRPAP (U1.54), SV601124B_Configuration pins (R5.1 R6.2)
RXD0: SV601124B_Block_Diagram (R65.1), SV601124B_DP83867IRPAP (U1.44), SV601124B_Configuration pins (C1.2 R32.1 R34.2)
RXD1: SV601124B_Block_Diagram (R64.1), SV601124B_DP83867IRPAP (U1.45), SV601124B_Configuration pins (C2.2 R30.1 R31.2)
RXD2: SV601124B_Block_Diagram (R61.1), SV601124B_DP83867IRPAP (U1.46), SV601124B_Configuration pins (C5.2 R28.1 R29.2)
RXD3: SV601124B_Block_Diagram (R51.1), SV601124B_DP83867IRPAP (U1.47), SV601124B_Configuration pins (C6.2 R26.1 R27.2)
RXD4: SV601124B_Block_Diagram (J9.15 R74.2), SV601124B_DP83867IRPAP (U1.48), SV601124B_Configuration pins (R290.1 R292.2)
RXD5: SV601124B_Block_Diagram (J9.13 R72.2), SV601124B_DP83867IRPAP (U1.49), SV601124B_Configuration pins (R12.1 R13.2)
RXD6: SV601124B_Block_Diagram (J9.11 R59.1), SV601124B_DP83867IRPAP (U1.50), SV601124B_Configuration pins (R10.1 R11.2)
RXD7: SV601124B_Block_Diagram (J9.9 R49.1), SV601124B_DP83867IRPAP (U1.51), SV601124B_Configuration pins (R37.1)
TX_CLK: SV601124B_Block_Diagram (J8.9 R80.1), SV601124B_DP83867IRPAP (U1.30)
TX_EN: SV601124B_Block_Diagram (J8.1 R79.1), SV601124B_DP83867IRPAP (U1.52)
TX_ER: SV601124B_Block_Diagram (J8.7 R84.1), SV601124B_DP83867IRPAP (U1.39)
TXD0: SV601124B_Block_Diagram (R66.1), SV601124B_DP83867IRPAP (U1.38), SV601124B_Configuration pins (C3.2)
TXD1: SV601124B_Block_Diagram (R68.1), SV601124B_DP83867IRPAP (U1.37), SV601124B_Configuration pins (C4.2)
TXD2: SV601124B_Block_Diagram (J8.21 R99.1), SV601124B_DP83867IRPAP (U1.36)
TXD3: SV601124B_Block_Diagram (J8.19 R83.1), SV601124B_DP83867IRPAP (U1.35)
TXD4: SV601124B_Block_Diagram (J8.17 R76.1), SV601124B_DP83867IRPAP (U1.34)
TXD5: SV601124B_Block_Diagram (J8.15 R85.1), SV601124B_DP83867IRPAP (U1.33)
TXD6: SV601124B_Block_Diagram (J8.13 R81.1), SV601124B_DP83867IRPAP (U1.32)
TXD7: SV601124B_Block_Diagram (J8.11 R75.1), SV601124B_DP83867IRPAP (U1.31)
VDD1P1: SV601124B_Block_Diagram (R52.2 R62.2 R67.1 R69.1), SV601124B_DP83867IRPAP (C324.2 C326.2 C328.2 C331.2)
VDDA1P8_AB: SV601124B_DP83867IRPAP (U1.64), SV601124B_Power_Supply (R95.1)
VDDA1P8_CD: SV601124B_DP83867IRPAP (U1.17), SV601124B_Power_Supply (R96.1)
VDDA1V1: SV601124B_DP83867IRPAP (U1.8 U1.29 U1.42 U1.58), SV601124B_Power_Supply (7 pins)
VDDA2P5: SV601124B_Block_Diagram (R23.1 R58.2), SV601124B_DP83867IRPAP (C330.2 C332.2 U1.4 U1.12), SV601124B_Power_Supply (6 pins)
VDDIO: SV601124B_Block_Diagram (R22.1 R57.2), SV601124B_DP83867IRPAP (6 pins), SV601124B_Power_Supply (7 pins)

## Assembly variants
001: not fitted C1 C2 C3 C4 C5 C6 C15 C19 C70 C267 C318 C319 FID1 FID2 FID3 J2 J3 J4 J5 J6 J7 J11 J13 P1 R1 R2 R3 R4 R5 R6 R10 R11 R12 R13 R15 R16 R17 R18 R19 R20 R21 R22 R23 R24 R25 R26 R27 R28 R29 R30 R31 R32 R33 R34 R39 R40 R41 R44 R46 R47 R48 R49 R52 R53 R54 R55 R56 R57 R58 R59 R60 R62 R63 R70 R71 R72 R74 R75 R76 R78 R79 R80 R81 R83 R84 R85 R88 R92 R95 R96 R97 R99 R100 R101 R102 R103 R104 R105 R106 R107 R108 R109 R110 R154 R177 R290 R292 R352 R660 R920 R921 R922 R923 R924 U3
